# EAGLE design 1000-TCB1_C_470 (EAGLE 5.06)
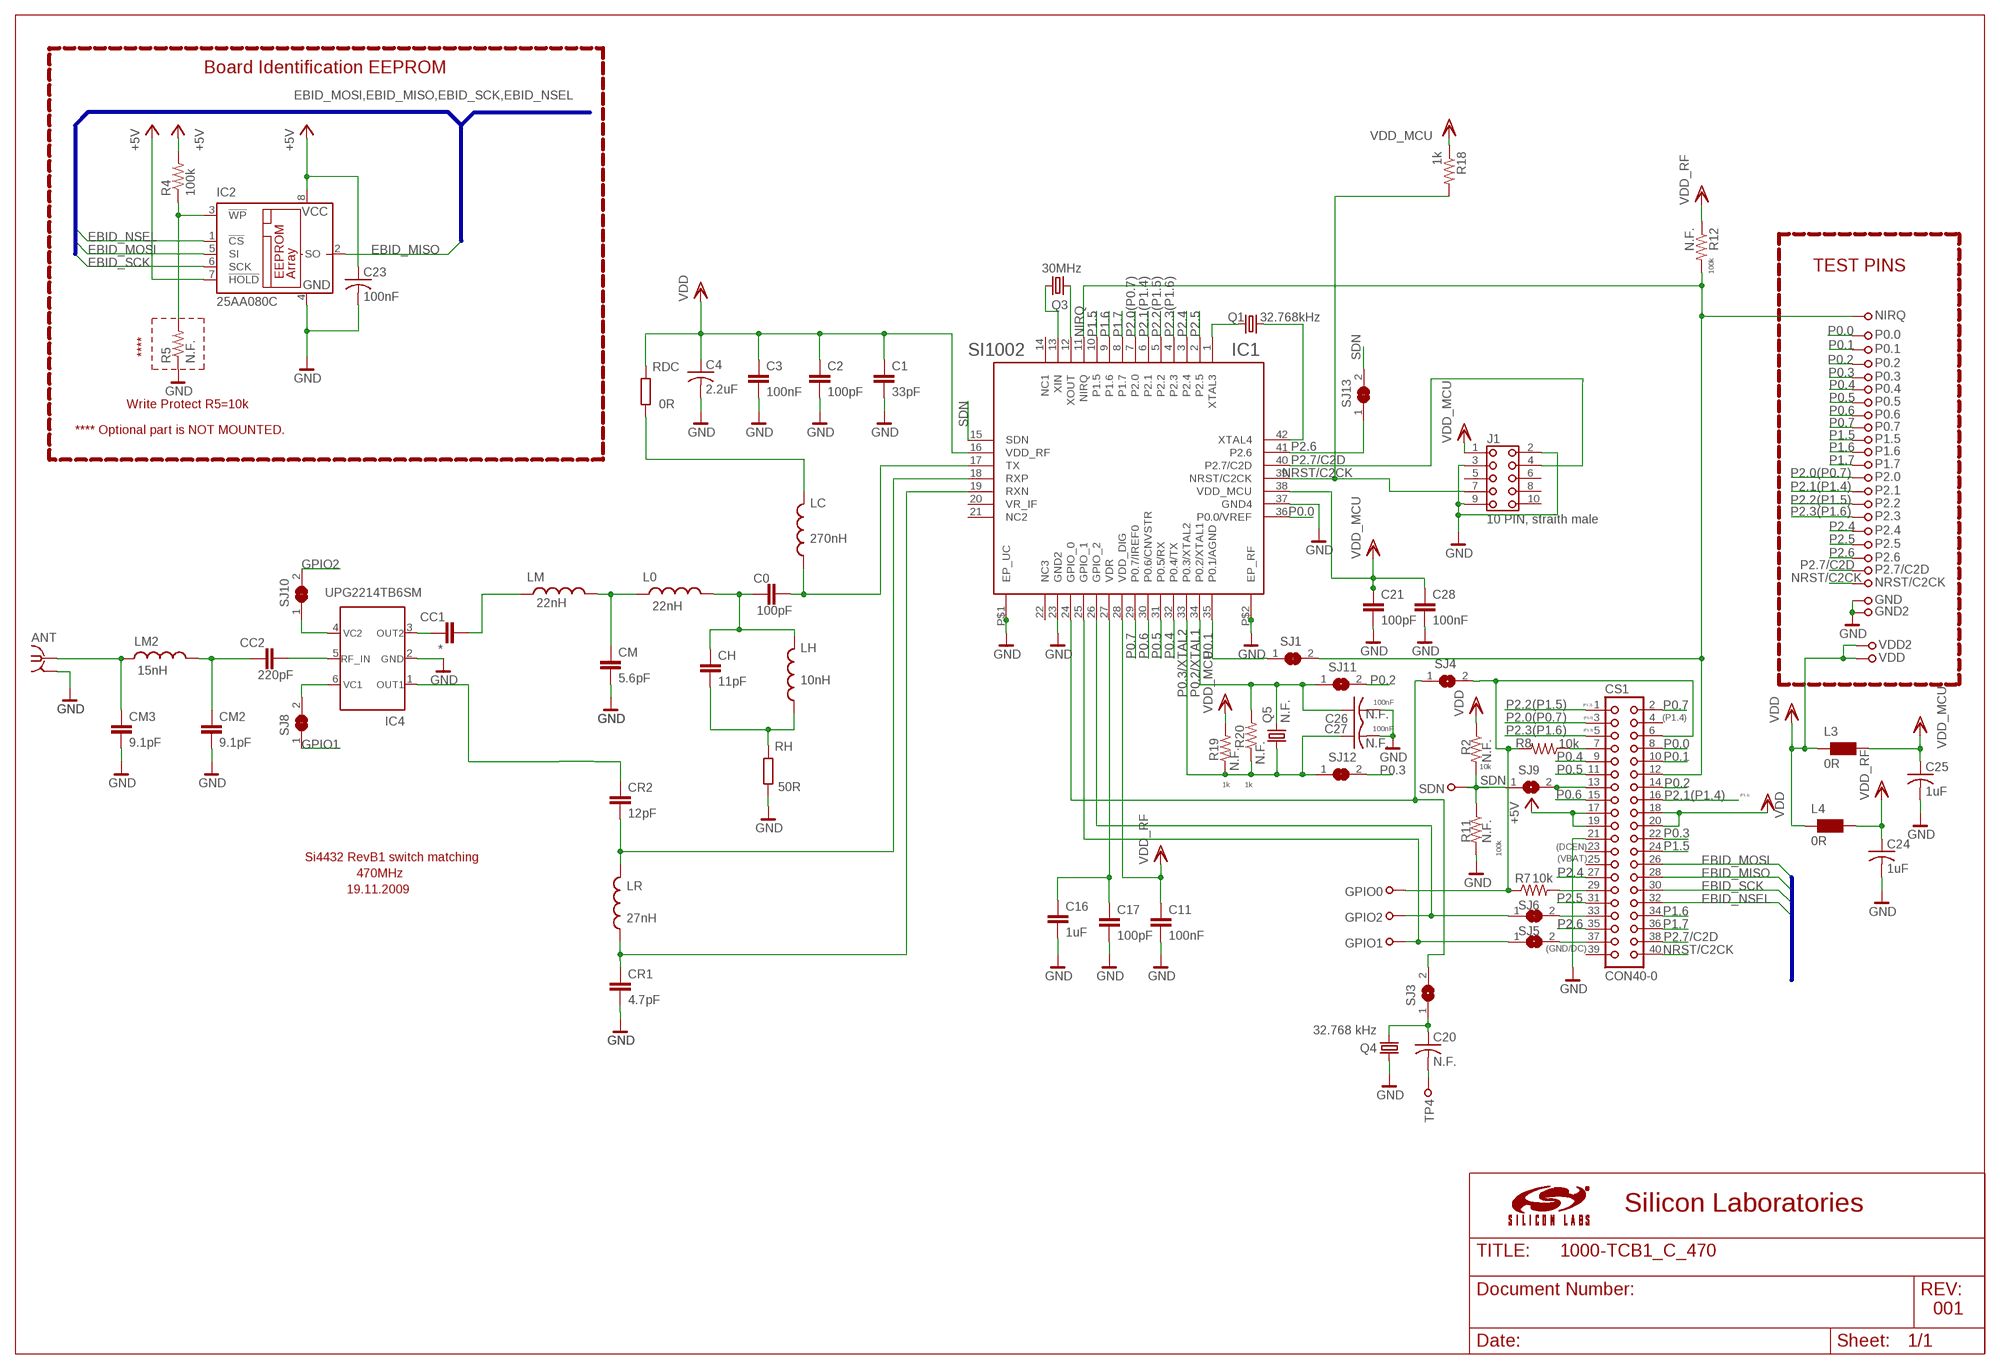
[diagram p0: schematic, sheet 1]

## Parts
ANT  BU-SMA-V  [BU-SMA-V]
C0  100pF  C-EUC0402S  [C0402S]
C1  33pF  C-EUC0402S  [C0402S]
C2  100pF  C-EUC0402S  [C0402S]
C3  100nF  C-EUC0402S  [C0402S]
C4  2.2uF  C-USC0603K  [C0603K]
C11  100nF  C-EUC0402S  [C0402S]
C16  1uF  C-EUC0402S  [C0402S]
C17  100pF  C-EUC0402S  [C0402S]
C20  N.F.  C-USC0603K  [C0603K]
C21  100pF  C-EUC0402S  [C0402S]
C23  100nF  C-USC0603K  [C0603K]
C24  1uF  C-USC0603K  [C0603K]
C25  1uF  C-USC0603K  [C0603K]
C26  N.F.  C-USC0603K  [C0603K]
C27  N.F.  C-USC0603K  [C0603K]
C28  100nF  C-EUC0402S  [C0402S]
CC1  *  C-EUC0402S  [C0402S]
CC2  220pF  C-EUC0402S  [C0402S]
CH  11pF  C-EUC0402S  [C0402S]
CM  5.6pF  C-EUC0402S  [C0402S]
CM2  9.1pF  C-EUC0402S  [C0402S]
CM3  9.1pF  C-EUC0402S  [C0402S]
CR1  4.7pF  C-EUC0402S  [C0402S]
CR2  12pF  C-EUC0402S  [C0402S]
CS1  CON40-0  [PANDUIT-057-040-0-INTEGRATION]
GND  TESTPOINT39MIL  [TESTPOINT1,0]
GND2  TESTPOINT39MIL  [TESTPOINT1,0]
GPIO0  TESTPOINT39MIL  [TESTPOINT1,0]
GPIO1  TESTPOINT39MIL  [TESTPOINT1,0]
GPIO2  TESTPOINT39MIL  [TESTPOINT1,0]
IC1  SI1002  SI1001NORMAL  [QFN42_MCM]
IC2  25AA080C  25AA040ST  [TSSOP8]
IC4  UPG2214TB6SM  [6-PIN_SUPER_MINIMOLD]
J1  10 PIN, straith male  PIN10PANDUIT  [PANDUIT-057-010-1]
L0  22nH  L-USL0402S  [L0402S]
L3  0R  FERRITE  [FERRITE0805]
L4  0R  FERRITE  [FERRITE0805]
LC  270nH  L-USL0402S  [L0402S]
LH  10nH  L-USL0402S  [L0402S]
LM  22nH  L-USL0402S  [L0402S]
LM2  15nH  L-USL0402S  [L0402S]
LR  27nH  L-USL0402S  [L0402S]
NIRQ  TESTPOINT39MIL  [TESTPOINT1,0]
NRST/C2CK  TESTPOINT39MIL  [TESTPOINT1,0]
P0.0  TESTPOINT39MIL  [TESTPOINT1,0]
P0.1  TESTPOINT39MIL  [TESTPOINT1,0]
P0.2  TESTPOINT39MIL  [TESTPOINT1,0]
P0.3  TESTPOINT39MIL  [TESTPOINT1,0]
P0.4  TESTPOINT39MIL  [TESTPOINT1,0]
P0.5  TESTPOINT39MIL  [TESTPOINT1,0]
P0.6  TESTPOINT39MIL  [TESTPOINT1,0]
P0.7  TESTPOINT39MIL  [TESTPOINT1,0]
P1.5  TESTPOINT39MIL  [TESTPOINT1,0]
P1.6  TESTPOINT39MIL  [TESTPOINT1,0]
P1.7  TESTPOINT39MIL  [TESTPOINT1,0]
P2.0  TESTPOINT39MIL  [TESTPOINT1,0]
P2.1  TESTPOINT39MIL  [TESTPOINT1,0]
P2.2  TESTPOINT39MIL  [TESTPOINT1,0]
P2.3  TESTPOINT39MIL  [TESTPOINT1,0]
P2.4  TESTPOINT39MIL  [TESTPOINT1,0]
P2.5  TESTPOINT39MIL  [TESTPOINT1,0]
P2.6  TESTPOINT39MIL  [TESTPOINT1,0]
P2.7/C2D  TESTPOINT39MIL  [TESTPOINT1,0]
Q1  32.768kHz  CRYSTAL-SMD3215_TST  [SMD3215_XTAL]
Q3  30MHz  CRYSTAL-4PINSX-2520-NEW1  [QUARTZ_SIWARD_2520_NEW1]
Q4  32.768 kHz  CRYSTAL32SL  [SMQ32SL]
Q5  N.F.  CRYTALHC49U-V  [HC49U-V]
R2  N.F.  R-US_R0603  [R0603@1]
R4  100k  R-US_R0603  [R0603@1]
R5  N.F.  R-US_R0603  [R0603@1]
R7  10k  R-US_R0603  [R0603@1]
R8  10k  R-US_R0603  [R0603@1]
R11  N.F.  R-US_R0603  [R0603@1]
R12  N.F.  R-US_R0603  [R0603@1]
R18  1k  R-US_R0603  [R0603@1]
R19  1k  R-US_R0603  [R0603@1]
R20  N.F.  R-US_R0603  [R0603@1]
RDC  0R  R-EU_R0402S  [R0402S]
RH  50R  R-EU_R0402S  [R0402S]
SDN  TESTPOINT39MIL  [TESTPOINT1,0]
SJ1  JUMPER_SMD_0402_1  [JUMPER_SMD_0402_1]
SJ3  JUMPER_SMD_0402_OPEN  [JUMPER_SMD_0402_OPEN_1]
SJ4  JUMPER_SMD_0402_OPEN  [JUMPER_SMD_0402_OPEN_1]
SJ5  JUMPER_SMD_0402_1  [JUMPER_SMD_0402_1]
SJ6  JUMPER_SMD_0402_1  [JUMPER_SMD_0402_1]
SJ8  JUMPER_SMD_0402_1  [JUMPER_SMD_0402_1]
SJ9  JUMPER_SMD_0402_OPEN  [JUMPER_SMD_0402_OPEN_1]
SJ10  JUMPER_SMD_0402_1  [JUMPER_SMD_0402_1]
SJ11  JUMPER_SMD_0402_1  [JUMPER_SMD_0402_1]
SJ12  JUMPER_SMD_0402_1  [JUMPER_SMD_0402_1]
SJ13  JUMPER_SMD_0402_1  [JUMPER_SMD_0402_1]
TP4  TESTPOINT39MIL  [TESTPOINT1,0]
VDD  TESTPOINT39MIL  [TESTPOINT1,0]
VDD2  TESTPOINT39MIL  [TESTPOINT1,0]

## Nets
+5V: C23.1 CS1.17 CS1.19 IC2.7(!HOLD) IC2.8(VCC) R4.2
EBID_MISO: CS1.28 IC2.2(SO)
EBID_MOSI: CS1.26 IC2.5(SI)
EBID_NSEL: CS1.32 IC2.1(!CS)
EBID_SCK: CS1.30 IC2.6(SCK)
GND: ANT.2(GND) C1.P$2 C2.P$2 C3.P$2 C4.2 C11.P$2 C16.P$2 C17.P$2 C21.P$2 C23.2 C24.2 C25.2 C26.2 C27.2 C28.P$2 CM2.P$2 CM3.P$2 CM.P$2 CR1.P$2 CS1.21 GND2.1 GND.1 IC1.23(GND2) IC1.37(GND4) IC1.EP1(GND5) IC1.EP2(GND6) IC1.EP3(GND7) IC1.EP4(GND8) IC1.EP5(GND9) IC1.EP6(GND10) IC1.EP7(GND11) IC1.EP8(GND12) IC1.P$1(EP_UC) IC1.P$2(EP_RF) IC2.4(GND) IC4.2 J1.2 J1.3 J1.9 Q4.1 R5.1 R11.2 RH.P$1
GPIO0: CS1.6 GPIO0.1 R7.1 R8.2 SJ4.2
GPIO1: GPIO1.1 IC1.25(GPIO_1) SJ5.1 SJ8.1
GPIO2: GPIO2.1 IC1.26(GPIO_2) SJ6.1 SJ10.2
N$1: C0.P$2 IC1.17(TX) LC.P$1
N$5: CS1.29 R7.2
N$6: CS1.33 SJ6.2
N$8: CS1.37 SJ5.2
N$9: CS1.7 R8.1
N$11: C0.P$1 CH.P$1 L0.P$2 LH.P$2
N$13: C20.1 Q4.4 SJ3.1
N$14: CC2.P$1 CM2.P$1 LM2.P$2
N$19: IC1.24(GPIO_0) SJ3.2 SJ4.1
N$20: CR2.P$2 IC1.18(RXP) LR.P$2
N$22: CR1.P$1 IC1.19(RXN) LR.P$1
N$23: LC.P$2 RDC.P$1
N$25: CC2.P$2 IC4.5
N$26: C20.2 TP4.1
N$29: IC4.6 SJ8.2
N$32: CC1.P$1 IC4.3
N$33: CH.P$2 LH.P$1 RH.P$2
N$34: IC1.12(XOUT) Q3.3
N$35: IC1.13(XIN) Q3.1
N$36: C16.P$1 C17.P$1 IC1.27(VDR)
N$38: IC4.4 SJ10.1
N$39: CC1.P$2 LM.P$1
N$41: IC2.3(!WP) R4.1 R5.2
N$45: IC1.1(XTAL3) Q1.X2
N$46: IC1.42(XTAL4) Q1.X1
N$48: CS1.13 SJ9.2
NIRQ: CS1.12 IC1.11(NIRQ) NIRQ.1 R12.2 SJ1.2
NRST/C2CK: CS1.40 IC1.39(NRST/C2CK) J1.7 NRST/C2CK.1 R18.2
P0.0: CS1.8 IC1.36(P0.0/VREF) P0.0.1
P0.1: CS1.10 IC1.35(P0.1/AGND) P0.1.1 SJ1.1
P0.2: CS1.14 P0.2.1 SJ11.2
P0.2/XTAL1: C26.1 IC1.34(P0.2/XTAL1) Q5.2 R20.2 SJ11.1
P0.3: CS1.22 P0.3.1 SJ12.2
P0.3/XTAL2: C27.1 IC1.33(P0.3/XTAL2) Q5.1 R19.1 R20.1 SJ12.1
P0.4: CS1.9 IC1.32(P0.4/TX) P0.4.1
P0.5: CS1.11 IC1.31(P0.5/RX) P0.5.1
P0.6: CS1.15 IC1.30(P0.6/CNVSTR) P0.6.1
P0.7: CS1.2 IC1.29(P0.7/IREF0) P0.7.1
P1.5: CS1.24 IC1.10(P1.5) P1.5.1
P1.6: CS1.34 IC1.9(P1.6) P1.6.1
P1.7: CS1.36 IC1.8(P1.7) P1.7.1
P2.0(P0.7): CS1.3 IC1.7(P2.0) P2.0.1
P2.1(P1.4): CS1.16 IC1.6(P2.1) P2.1.1
P2.2(P1.5): CS1.1 IC1.5(P2.2) P2.2.1
P2.3(P1.6): CS1.5 IC1.4(P2.3) P2.3.1
P2.4: CS1.27 IC1.3(P2.4) P2.4.1
P2.5: CS1.31 IC1.2(P2.5) P2.5.1
P2.6: CS1.35 IC1.41(P2.6) P2.6.1 SJ13.1
P2.7/C2D: CS1.38 IC1.40(P2.7/C2D) J1.4 P2.7/C2D.1
RX: CR2.P$1 IC4.1
SDN: IC1.15(SDN) R2.2 R11.1 SDN.1 SJ9.1 SJ13.2
TX: ANT.1 CM3.P$1 LM2.P$1
TX3: CM.P$1 L0.P$1 LM.P$2
VCC_MCU: C21.P$1 C25.1 C28.P$1 IC1.38(VDD_MCU) J1.1 L3.2 R18.1 R19.2 ; supply symbol labelled VDD_MCU
VDD: C1.P$1 C2.P$1 C3.P$1 C4.1 CS1.18 CS1.20 IC1.16(VDD_RF) L3.1 L4.1 R2.1 RDC.P$2 VDD2.1 VDD.1
VDD_RF: C11.P$1 C24.1 IC1.28(VDD_DIG) L4.2 R12.1
Unconnected: CS1.4 CS1.23 CS1.25 CS1.39 IC1.14(NC1) IC1.21(NC2) IC1.22(NC3) J1.5 J1.6 J1.8 J1.10

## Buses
EBID_MOSI,EBID_MISO,EBID_SCK,EBID_NSEL

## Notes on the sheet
- Board Identification EEPROM
- 100k | TEST PINS
- ****
- Write Protect R5=10k
- **** Optional part is NOT MOUNTED.
- 100nF
- (P1.2)
- N.F. | (P1.0)
- (P1.4)
- 100nF | (P1.3)
- N.F.
- N.F. | N.F.
- 10k
- 1k | 1k
- (P1.1)
- (DCEN)
- 100k
- Si4432 RevB1 switch matching | (VBAT)
- 470MHz
- 19.11.2009
- (GND/DC)
- Silicon Laboratories
- 001

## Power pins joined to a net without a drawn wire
GND: ANT.3(GND) ANT.4(GND) ANT.5(GND) Q3.2(GND) Q3.4(GND)
VR_IF: IC1.20(VR_IF)

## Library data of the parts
ANT = lve:BU-SMA-V: FEMALE SMA CONNECTOR Radiall distributor RS 112-3794
C0 C1-C3 C11 C16 C17 C21 C28 CC1 CC2 CH CM CM2 CM3 CR1 CR2 = rcl:C-EU: CAPACITOR, European symbol
C4 C20 C23-C27 = rcl:C-US: CAPACITOR, American symbol
CS1 = lve:CON40
GND GND2 GPIO0 GPIO1 GPIO2 NIRQ NRST/C2CK P0.0 P0.1-P0.7 P1.5-P1.7 P2.0 P2.1-P2.6 P2.7/C2D SDN TP4 VDD VDD2 = lve:TESTPOINT
IC1 = SiLabsMCU:SI1001
IC2 = microchip:25*: Serial EEPROM 4 K, SPI bus
IC4 = lve:UPG2214TB
J1 = lve:PIN10
L0 LC LH LM LM2 LR = rcl:L-US: INDUCTOR, American symbol
L3 L4 = lve:FERRITE
Q1 = dzo:CRYSTAL-SMD3215_TST
Q3 = lve:CRYSTAL-4PIN
Q4 = lve:CRYSTAL
Q5 = mlu:CRYTAL: CRYSTAL
R2 R4 R5 R7 R8 R11 R12 R18-R20 = rcl:R-US_: RESISTOR, American symbol
RDC RH = rcl:R-EU_: RESISTOR, European symbol
SJ1 SJ5 SJ6 SJ8 SJ10-SJ13 = tab:JUMPER_SMD_0402_1
SJ3 SJ4 SJ9 = tab:JUMPER_SMD_0402_OPEN

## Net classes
1 dgnd: clearance 0.508 mm

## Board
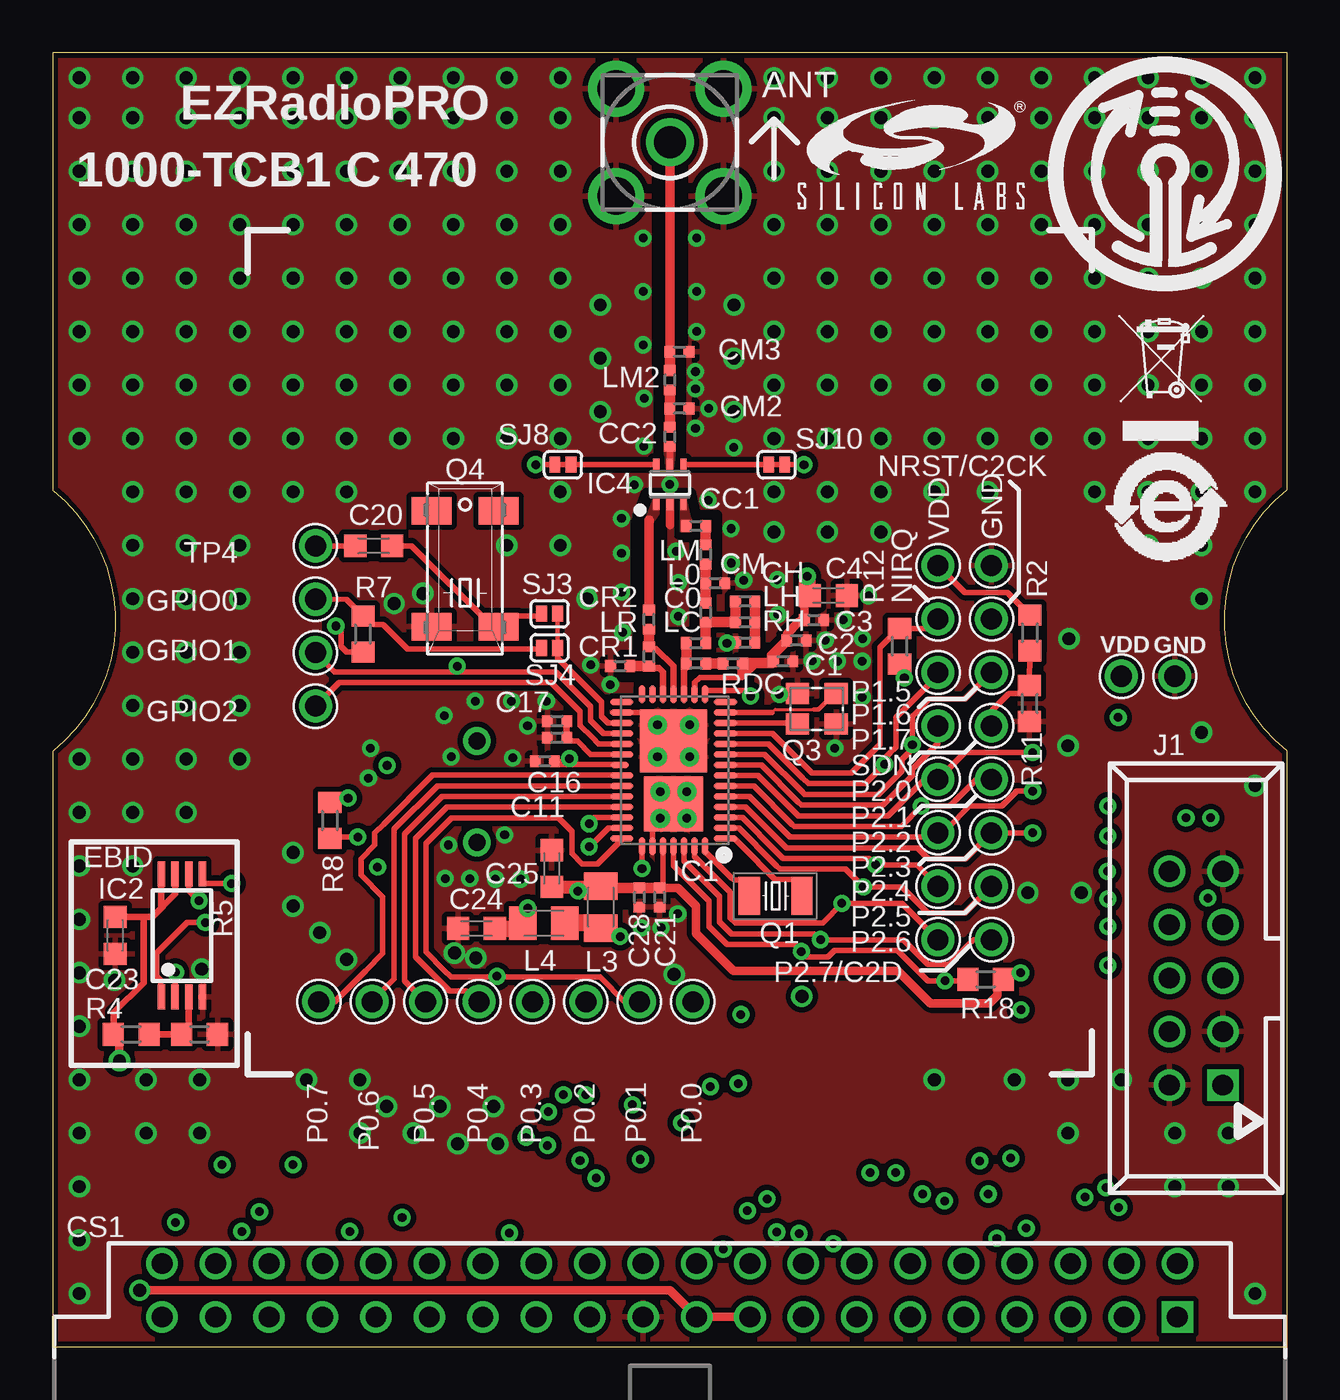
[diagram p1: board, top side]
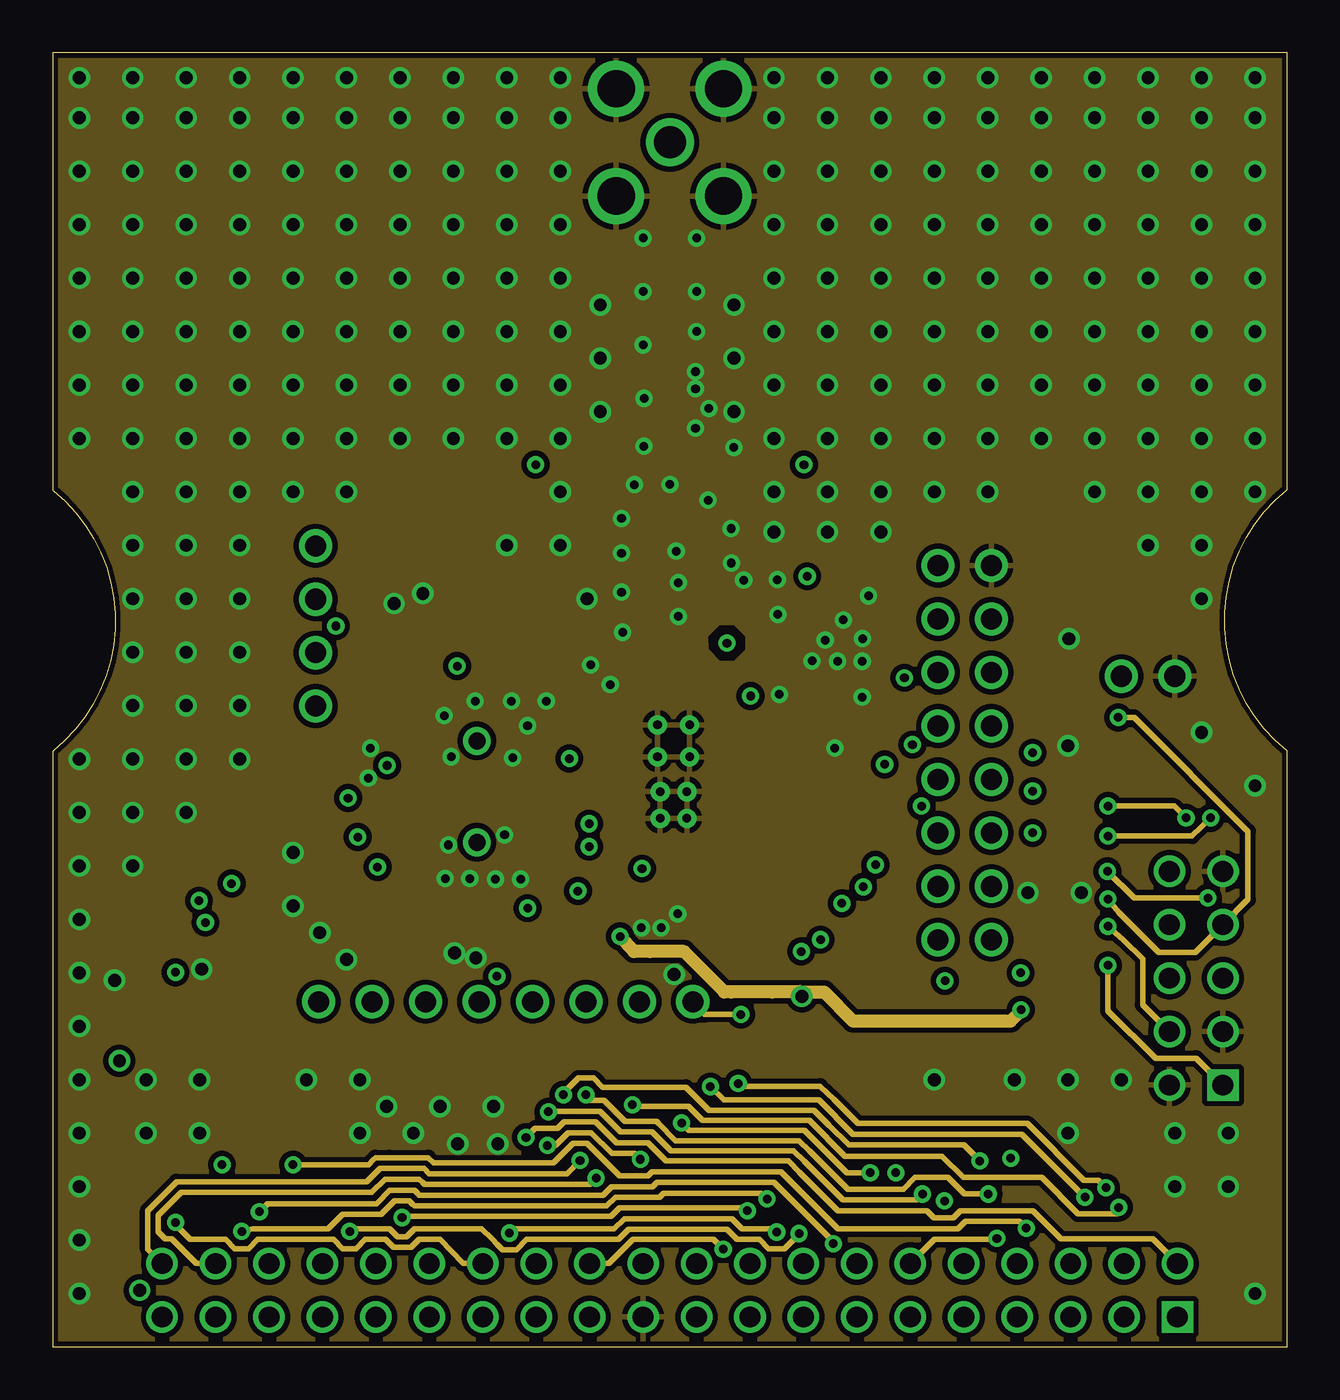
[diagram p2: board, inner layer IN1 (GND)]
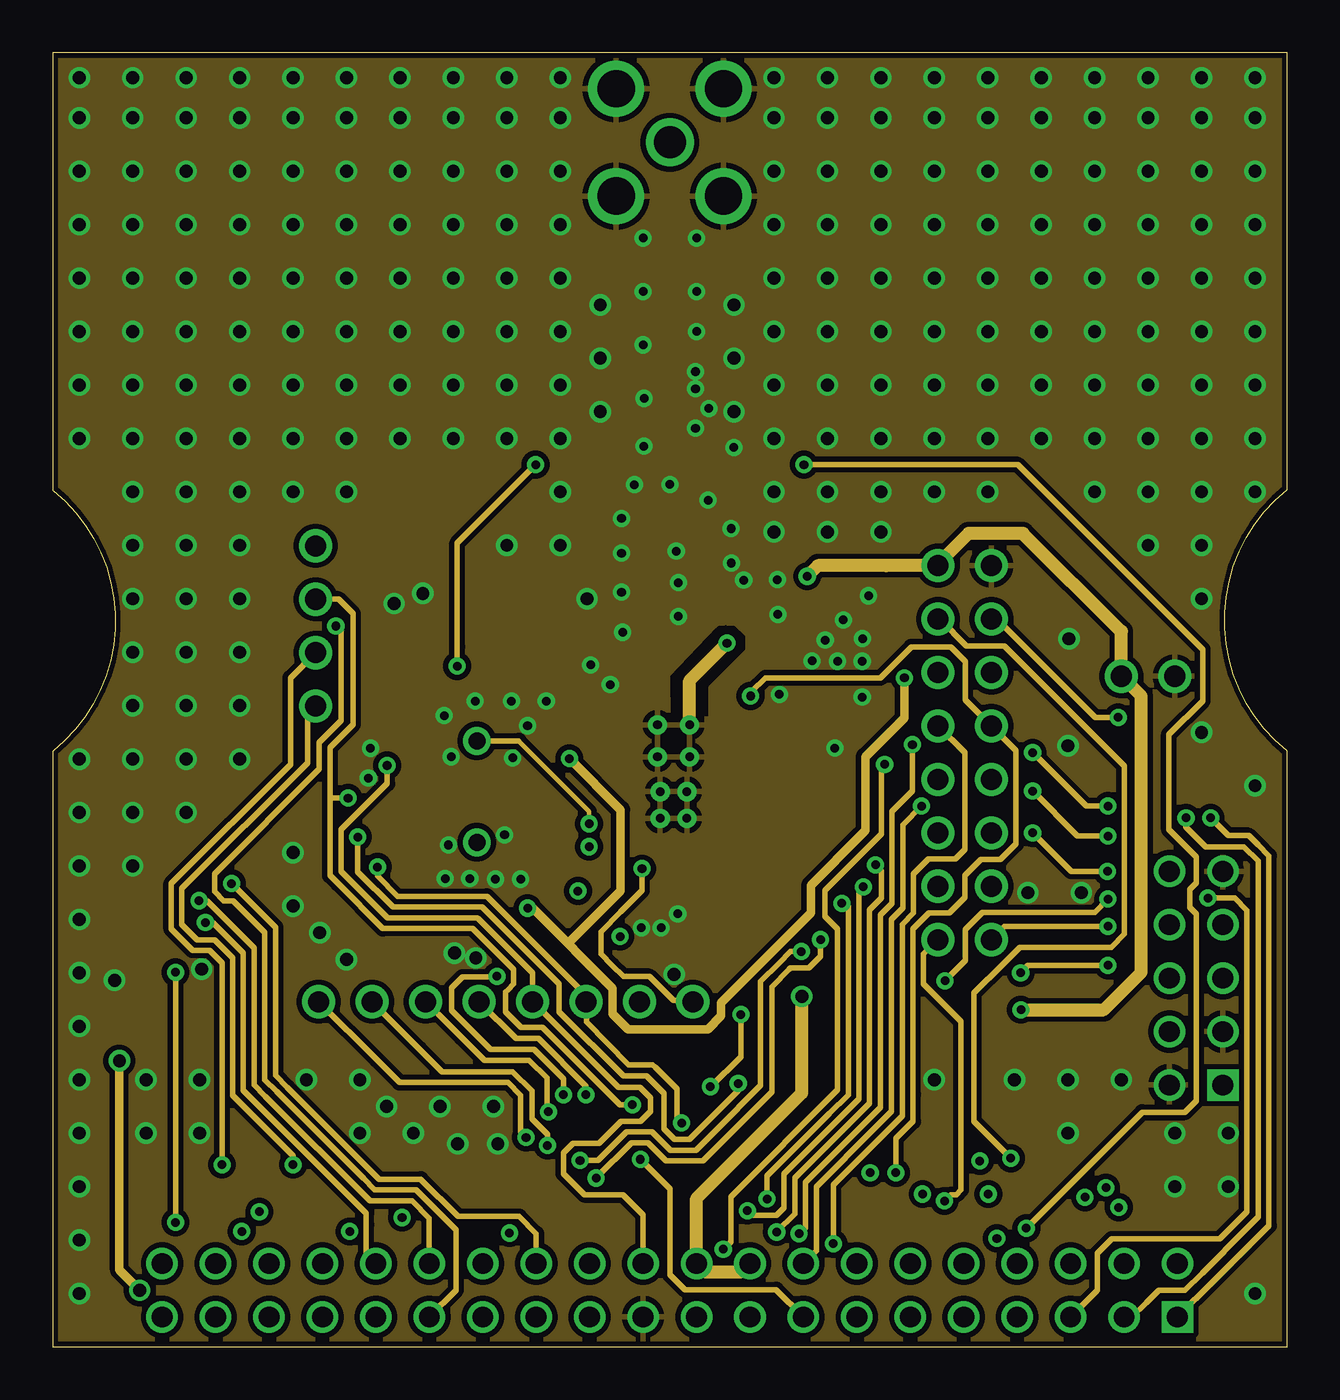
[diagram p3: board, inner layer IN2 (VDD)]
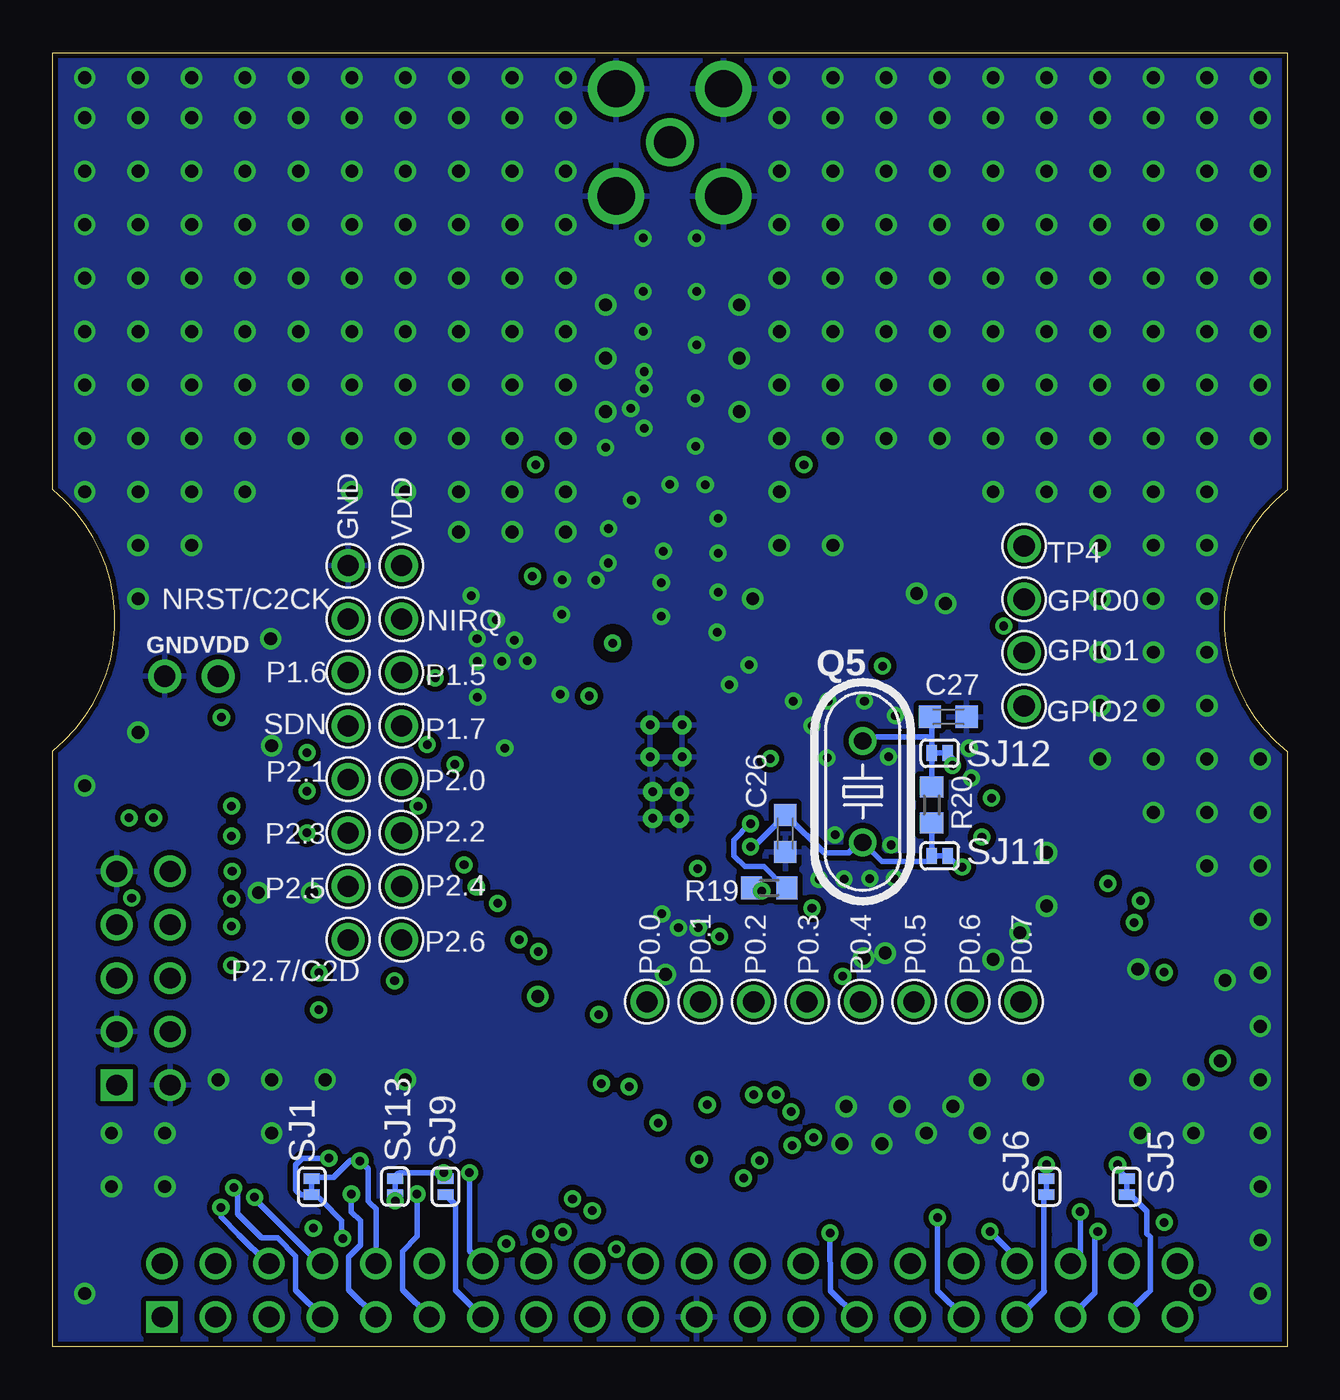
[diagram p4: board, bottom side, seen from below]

Size 58.67 x 61.52 mm. Coordinates in mm from the lower left corner, seen from the top.
Outline: 0,28.3 0,0 58.67,0 58.67,28.32 arc-102 58.67,40.74 58.67,61.52 0,61.52 0,40.72 0.03,40.69 arc-102 0,28.3
Copper layers (1*2*3*16): Top 0.0356mm / dielectric 0.5mm / IN1 (GND) 0.0356mm / dielectric 0.5mm / IN2 (VDD) 0.0356mm / dielectric 0.5mm / Bottom 0.0356mm
Design rules "TAMARA *": minimum track width 8mil, minimum drill 13mil, track to track 10mil, track to pad 10mil, pad to pad 10mil, via to via 10mil, smd to smd 0mil, copper to edge 10mil, drill to drill 8mil, minimum pad ring 10mil, minimum via ring 8mil, stop-mask expansion 4mil, vias tented up to drill 24mil, thermal gap 10mil
tRestrict: 34 lines
bRestrict: area 31.4,32.8 to 32.7,34.1; 2 lines

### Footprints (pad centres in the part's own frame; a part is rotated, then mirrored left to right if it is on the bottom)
BU-SMA-V = drill 1.524 pad 2.286 round: 1 0,0 | drill 1.778 pad 2.667 round: 2 -2.55,2.55; 3 2.55,2.55; 4 2.55,-2.55; 5 -2.55,-2.55
C0402S = smd 0.508 x 0.559: P$1 -0.457,0; P$2 0.457,0
C0603K = smd 1.05 x 1.08: 1 -0.875,0; 2 0.875,0
PANDUIT-057-040-0-INTEGRATION = drill 0.991 square: 1 -24.13,-1.27 | drill 0.991 round: 2 -24.13,-3.81; 3 -21.59,-1.27; 4 -21.59,-3.81; 5 -19.05,-1.27; 6 -19.05,-3.81; 7 -16.51,-1.27; 8 -16.51,-3.81; 9 -13.97,-1.27; 10 -13.97,-3.81; 11 -11.43,-1.27; 12 -11.43,-3.81; 13 -8.89,-1.27; 14 -8.89,-3.81; 15 -6.35,-1.27; 16 -6.35,-3.81; 17 -3.81,-1.27; 18 -3.81,-3.81; 19 -1.27,-1.27; 20 -1.27,-3.81; 21 1.27,-1.27; 22 1.27,-3.81; 23 3.81,-1.27; 24 3.81,-3.81; 25 6.35,-1.27; 26 6.35,-3.81; 27 8.89,-1.27; 28 8.89,-3.81; 29 11.43,-1.27; 30 11.43,-3.81; 31 13.97,-1.27; 32 13.97,-3.81; 33 16.51,-1.27; 34 16.51,-3.81; 35 19.05,-1.27; 36 19.05,-3.81; 37 21.59,-1.27; 38 21.59,-3.81; 39 24.13,-1.27; 40 24.13,-3.81
TESTPOINT1,0 = drill 1 pad 1.575 round: 1 0,0
QFN42_MCM = smd 1.1 x 0.3: 1 -2.46,3.25; 2 -2.46,2.75; 3 -2.46,2.25; 4 -2.46,1.75; 5 -2.46,1.25; 6 -2.46,0.75; 7 -2.46,0.25; 8 -2.46,-0.25; 9 -2.46,-0.75; 10 -2.46,-1.25; 11 -2.46,-1.75; 12 -2.46,-2.25; 13 -2.46,-2.75; 14 -2.46,-3.25; 22 2.46,-3.25; 23 2.46,-2.75; 24 2.46,-2.25; 25 2.46,-1.75; 26 2.46,-1.25; 27 2.46,-0.75; 29 2.46,0.25; 30 2.46,0.75; 31 2.46,1.25; 32 2.46,1.75; 33 2.46,2.25; 34 2.46,2.75; 35 2.46,3.25 | smd 0.3 x 0.85: 15 -1.5,-3.61; 16 -1,-3.61; 17 -0.5,-3.61; 18 0,-3.61; 19 0.5,-3.61; 20 1,-3.61; 21 1.5,-3.61; 36 1.5,3.61; 37 1,3.61; 38 0.5,3.61; 39 0,3.61; 40 -0.5,3.61; 41 -1,3.61; 42 -1.5,3.61 | smd 0.85 x 0.3: 28 2.56,-0.25 | drill 0.406 round: EP1 -0.635,2.286; EP2 0.635,2.286; EP3 -0.635,1.016; EP4 0.635,1.016; EP5 -0.762,-0.635; EP6 0.762,-0.635; EP7 -0.762,-2.159; EP8 0.762,-2.159 | smd 2.8 x 2.6: P$1 0,1.6 | smd 3.2 x 3: P$2 0,-1.4
TSSOP8 = smd 0.35 x 1.2: 1 -0.975,-2.925; 2 -0.325,-2.925; 3 0.325,-2.925; 4 0.975,-2.925; 5 0.975,2.925; 6 0.325,2.925; 7 -0.325,2.925; 8 -0.975,2.925
6-PIN_SUPER_MINIMOLD = smd 0.55 x 0.3: 1 -0.948,0.65; 2 -0.948,0; 3 -0.948,-0.65; 4 0.948,-0.65; 5 0.948,0; 6 0.948,0.65
PANDUIT-057-010-1 = drill 0.991 square: 1 -5.08,-1.27 | drill 0.991 round: 2 -5.08,1.27; 3 -2.54,-1.27; 4 -2.54,1.27; 5 0,-1.27; 6 0,1.27; 7 2.54,-1.27; 8 2.54,1.27; 9 5.08,-1.27; 10 5.08,1.27
L0402S = smd 0.508 x 0.559: P$1 -0.457,0; P$2 0.457,0
FERRITE0805 = smd 1.3 x 1.6: 1 -1,0; 2 1,0
SMD3215_XTAL = smd 1 x 1.8: X1 -1.23,0.016; X2 1.27,0.016
QUARTZ_SIWARD_2520_NEW1 = smd 1.1 x 1: 1 -0.925,-0.725; 2 0.925,-0.725; 3 0.925,0.725; 4 -0.925,0.725
SMQ32SL = smd 1.3 x 1.9: 1 -2.75,1.6; 2 2.75,1.6; 3 2.75,-1.6; 4 -2.75,-1.6
HC49U-V = drill 0.813 round: 1 -2.413,0; 2 2.413,0
R0603@1 = smd 1 x 1.1: 1 -0.85,0; 2 0.85,0
R0402S = smd 0.508 x 0.559: P$1 -0.457,0; P$2 0.457,0
JUMPER_SMD_0402_1 = smd 0.508 x 0.762: 1 -0.381,0; 2 0.381,0
JUMPER_SMD_0402_OPEN_1 = smd 0.508 x 0.762: 1 -0.381,0; 2 0.381,0

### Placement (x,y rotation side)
ANT  29.34,57.25 0 top
C0  30.58,33.45 180 top
C1  34.72,32.59 0 top
C2  35.36,33.58 0 top
C3  36.2,34.54 0 top
C4  36.88,35.71 0 top
C11  23.39,27.84 180 top
C16  23.98,28.96 180 top
C17  23.98,29.74 180 top
C20  15.27,38.07 180 top
C21  28.85,21.36 270 top
C23  2.97,19.56 270 top
C24  20.14,19.89 180 top
C25  23.72,22.73 90 top
C26  23.85,24.41 270 bottom
C27  16.1,29.95 0 bottom
C28  27.89,21.36 270 top
CC1  30.58,39.01 0 top
CC2  29.34,43.26 270 top
CH  32.92,35.43 0 top
CM  31.5,36.3 0 top
CM2  29.79,44.6 0 top
CM3  29.79,47.29 0 top
CR1  26.97,32.36 180 top
CR2  28.35,34.57 270 top
CS1  29.34,0.15 180 top
E$1  [TRANSCEIVE-ICON06]  52.86,56.06 0 top
GND  44.63,37.13 0 top
GND2  53.34,31.88 0 top
GPIO0  12.5,35.53 0 top
GPIO1  12.5,32.99 0 top
GPIO2  12.5,30.45 0 top
IC1  29.51,27.41 180 top
IC2  6.15,19.56 0 top
IC4  29.34,41 90 top
J1  54.36,17.53 90 top
L0  31.04,34.9 270 top
L3  26.06,20.9 90 top
L4  23.34,20.14 180 top
LC  30.58,32.49 0 top
LH  32.92,34.44 180 top
LM  31.04,37.67 270 top
LM2  29.34,45.95 270 top
LR  28.35,32.82 90 top
NIRQ  42.09,34.59 180 top
NRST/C2CK  44.63,34.59 0 top
P0.0  30.43,16.41 0 top
P0.1  27.89,16.41 0 top
P0.2  25.35,16.41 0 top
P0.3  22.81,16.41 0 top
P0.4  20.27,16.41 0 top
P0.5  17.73,16.41 0 top
P0.6  15.19,16.41 0 top
P0.7  12.65,16.41 0 top
P1.5  42.09,32.05 0 top
P1.6  44.63,32.05 0 top
P1.7  42.09,29.51 0 top
P2.0  42.09,26.97 0 top
P2.1  44.63,26.97 0 top
P2.2  42.09,24.43 0 top
P2.3  44.63,24.43 0 top
P2.4  42.09,21.89 0 top
P2.5  44.63,21.89 0 top
P2.6  42.09,19.35 0 top
P2.7/C2D  44.63,19.35 0 top
Q1  34.34,21.41 0 top
Q3  36.32,30.33 180 top
Q4  19.61,36.98 90 top
Q5  20.17,26.39 270 bottom
R2  46.45,33.94 270 top
R4  3.73,14.86 180 top
R5  6.99,14.86 180 top
R7  14.76,33.88 270 top
R8  13.18,25.02 90 top
R11  46.43,30.58 270 top
R12  40.26,33.3 90 top
R18  44.35,17.48 180 top
R19  24.61,21.82 180 bottom
R20  16.89,25.76 270 bottom
RDC  32.33,32.49 0 top
RH  32.92,33.48 0 top
SDN  44.63,29.51 0 top
SJ1  46.35,7.62 270 bottom
SJ3  23.62,34.85 0 top
SJ4  23.62,33.22 180 top
SJ5  7.62,7.62 270 bottom
SJ6  11.43,7.62 270 bottom
SJ8  24.26,41.94 0 top
SJ9  40.01,7.62 270 bottom
SJ10  34.42,41.94 0 top
SJ11  16.51,23.34 0 bottom
SJ12  16.51,28.22 0 bottom
SJ13  42.39,7.62 90 bottom
TP4  12.5,38.07 0 top
U$1  SILABS_LOGO  [SILABS_LOGO]  34.47,53.59 0 top
U$5  [ROHS_CHINA]  53.01,40.01 0 top
U$27  [NON-DISPOSABLE]  52.7,46.96 0 top
VDD  42.09,37.13 0 top
VDD2  50.8,31.88 0 top

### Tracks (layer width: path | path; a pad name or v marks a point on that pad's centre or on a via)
+5V  (via drill 0.61)
  Top 0.254: 4.33,20.43 4.32,20.45
  Top 0.305: IC2.8 5.17,20.87 4.75,20.45 | C23.1 3.48,20.45 4.32,20.45 4.75,20.45 | IC2.7 5.82,21.52 4.75,20.45 | R4.2 2.9,15.9 4.33,17.31 4.33,20.43
  Top 0.406: CS1.17 CS1.19 29.34,2.69 v4.14,2.69 | v3.17,13.6 3.17,14.66 3.17,14.86 R4.2
  IN2 (VDD) 0.406: v4.14,2.69 3.17,3.66 v3.17,13.6
EBID_MISO  (via drill 0.41)
  Top 0.254: IC2.2 5.82,17.89 v5.84,17.8
  IN1 (GND) 0.254: CS1.28 19.51,3.96 18.41,5.11 17.42,5.11 17.04,4.72 16.2,4.72 15.82,5.11 15.24,5.11 14.86,5.11 14.43,4.67 13.79,4.67 13.36,5.11 9.75,5.11 9.32,4.67 8.66,4.67 8.23,5.11 6.53,5.11 5.84,5.79 v5.84,5.92
  IN2 (VDD) 0.254: v5.84,5.92 v5.84,17.8
EBID_MOSI  (via drill 0.41 pad 0.81)
  Top 0.254: IC2.5 7.16,22.48 7.11,22.43 7.11,22.02 v8.51,22.02
  IN2 (VDD) 0.254: 8.48,21.95 v8.51,22.02 10.59,19.94 10.59,12.9 11.15,12.34 15.52,7.98 17.5,7.98 19.28,6.2 22.17,6.2 22.99,5.38 CS1.26
EBID_NSEL  (via drill 0.41)
  Top 0.254: 5.18,16.36 5.18,16.62 IC2.1 5.13,16.67 5.13,17.42 4.95,17.6 4.95,18.72 5.33,19.1 6.4,20.17 v7.26,20.17
  IN2 (VDD) 0.254: CS1.32 14.91,4.42 14.91,5.82 14.91,6.35 9.6,11.66 9.07,12.19 9.07,18.19 9.07,18.72 8.05,19.74 7.62,20.17 v7.26,20.17
EBID_SCK  (via drill 0.41 pad 0.81)
  Top 0.254: 6.48,22.61 IC2.6 6.48,21.69 v6.96,21.21
  IN2 (VDD) 0.254: CS1.30 17.91,6.1 17.08,6.93 16.08,6.93 15.09,6.93 10.11,11.91 9.58,12.45 9.58,18.62 9.58,18.97 7.87,20.68 7.34,21.21 v6.96,21.21
GND  (via drill 0.41 pad 0.81, 0.61, 0.61 pad 1.02)
  Top 0.203: IC1.P$2 29.52,28.78 28.8,29.49 28.75,29.54 IC1.P$2
  Top 0.254: IC1.P$1 28.88,25.09 28.52,24.73 IC1.37 | 28.83,29.49 IC1.P$2 28.82,29.5 28.16,30.16 IC1.23
  Top 0.406: IC1.P$2 29.46,28.81 | 28.82,29.5 28.8,29.5 28.8,29.49 28.8,29.57 IC1.EP8 | IC1.EP2 28.88,25.09 | 29.34,39.06 v29.34,41 | RH.P$1 32.05,33.48 v32.05,33.45
  Top 0.508: v25.57,32.42 25.74,32.44
  IN2 (VDD) 0.61: v32.05,33.45 30.28,31.67 30.28,29.59
  other vias: 1.27,2.54 38.48,30.89 36.1,32.61 38.48,32.59 37.58,34.56 36.72,33.59 38.5,33.67 34.54,31.01 2.95,17.42 6.99,10.16 38.78,35.7 29.71,20.58 27.99,19.92 34.48,34.82 34.45,36.47 32.27,37.26 27.09,33.97 32.25,38.9 37.18,28.46 22.25,22.23 18.66,22.26 22.58,29.52 18.61,30 21.48,24.34 18.94,28.05 1.27,5.08 1.27,7.62 1.27,12.7 1.27,15.24 1.27,17.78 1.27,20.32 1.27,22.86 1.27,25.4 3.81,27.94 3.81,25.4 6.35,25.4 6.35,27.94 8.89,27.94 3.81,22.86 3.81,30.48 6.35,30.48 8.89,30.48 6.35,33.02 3.81,33.02 3.81,35.56 6.35,35.56 8.89,35.56 8.89,33.02 13.97,40.64 11.43,40.64 8.89,38.1 6.35,38.1 3.81,38.1 3.81,40.64 8.89,40.64 8.89,43.18 8.89,45.72 6.35,45.72 3.81,45.72 3.81,43.18 1.27,45.72 1.27,48.26 1.27,50.8 1.27,53.34 1.27,55.88 3.81,55.88 3.81,53.34 3.81,50.8 3.81,48.26 3.81,58.42 3.81,60.33 1.27,60.33 1.27,58.42 8.89,48.26 8.89,58.42 8.89,55.88 8.89,53.34 8.89,50.8 8.89,60.33 6.35,43.18 6.35,55.88 6.35,53.34 6.35,50.8 6.35,48.26 6.35,58.42 6.35,60.33 16.51,45.72 16.51,43.18 16.51,55.88 16.51,53.34 16.51,50.8 16.51,48.26 16.51,58.42 16.51,60.33 19.05,45.72 19.05,43.18 19.05,55.88 19.05,53.34 19.05,50.8 19.05,48.26 19.05,58.42 19.05,60.33 21.59,45.72 21.59,43.18 21.59,55.88 21.59,53.34 21.59,50.8 21.59,48.26 21.59,58.42 21.59,60.33 24.13,45.72 24.13,43.18 24.13,55.88 24.13,53.34 24.13,50.8 24.13,48.26 24.13,58.42 24.13,60.33 13.97,45.72 13.97,43.18 13.97,55.88 13.97,53.34 13.97,50.8 13.97,48.26 13.97,58.42 13.97,60.33 11.43,45.72 11.43,43.18 11.43,55.88 11.43,53.34 11.43,50.8 11.43,48.26 11.43,58.42 11.43,60.33 41.91,45.72 39.37,45.72 36.83,45.72 34.29,45.72 34.29,48.26 34.29,50.8 34.29,53.34 34.29,55.88 36.83,55.88 36.83,53.34 36.83,50.8 36.83,48.26 36.83,58.42 36.83,60.33 34.29,60.33 34.29,58.42 41.91,48.26 41.91,58.42 41.91,55.88 41.91,53.34 41.91,50.8 41.91,60.33 39.37,55.88 39.37,53.34 39.37,50.8 39.37,48.26 39.37,58.42 39.37,60.33 49.53,45.72 49.53,55.88 49.53,53.34 49.53,50.8 49.53,48.26 49.53,58.42 49.53,60.33 52.07,45.72 52.07,55.88 52.07,53.34 52.07,50.8 52.07,48.26 52.07,58.42 52.07,60.33 54.61,45.72 54.61,55.88 54.61,53.34 54.61,50.8 54.61,48.26 54.61,58.42 54.61,60.33 57.15,45.72 57.15,55.88 57.15,53.34 57.15,50.8 57.15,48.26 57.15,58.42 57.15,60.33 46.99,45.72 46.99,55.88 46.99,53.34 46.99,50.8 46.99,48.26 46.99,58.42 46.99,60.33 44.45,45.72 44.45,55.88 44.45,53.34 44.45,50.8 44.45,48.26 44.45,58.42 44.45,60.33 41.91,43.18 39.37,43.18 49.53,40.64 49.53,43.18 52.07,40.64 52.07,43.18 54.61,40.64 54.61,43.18 57.15,43.18 46.99,43.18 44.45,43.18 39.37,38.73 52.07,38.1 54.61,38.1 36.83,43.18 34.29,43.18 24.13,38.1 21.59,38.1 57.15,2.54 29.64,37.82 26.51,31.48 28.07,47.62 30.61,52.7 30.56,46.35 31.19,44.6 32.38,42.75 36.83,38.73 39.37,40.64 41.91,40.64 44.45,40.64 34.29,38.73 15.01,27.03 15.11,28.46 16.23,35.33 21.81,30.69 23.46,30.69 20.09,30.69 21.86,28 21.16,9.65 20.12,18.49 19.83,22.26 21.05,22.23 18.82,23.86 17.6,35.81 18.41,11.43 17.14,10.16 15.88,11.43 28.93,19.92 29.54,17.7 48.31,33.66 37.31,32.59 28.11,42.81 28.12,45.09 31.16,40.24 32.85,36.44 24.13,40.64 34.29,40.64 36.83,40.64 7.09,17.96 53.34,10.16 55.88,10.16 55.88,7.62 11.43,23.5 11.43,20.95 19.25,9.65 20.95,11.43 14.61,10.16 14.61,12.7 12.06,12.7 50.8,12.7 48.26,12.7 41.91,12.7 53.34,7.62 46.35,21.59 48.26,28.57 54.61,35.56 54.61,29.21 57.15,26.67 13.97,18.41 12.7,19.68 19.1,18.72 6.35,40.64 1.27,43.18 57.15,40.64 6.99,12.7 4.45,10.16 4.45,12.7 1.27,10.16 1.27,27.94 48.26,10.16 45.72,12.7 48.9,21.59 25.4,35.56 26.04,46.99 26.04,49.53 26.04,44.45 32.38,44.45 32.38,46.99 32.38,49.53 30.56,45.54 30.56,43.66 28.07,50.16 28.07,52.7 30.61,50.16 30.61,48.26 27.04,35.87 27.04,37.73 27.04,39.38 29.74,36.32 29.74,34.72 27.65,40.98
  pour Bottom: 0,0 58.67,0 58.75,62.79 0.08,62.79
  pour Top (rank 2): 0,0 58.67,0 58.75,62.79 0.08,62.79
  pour IN2 (VDD) (isolate 0.254, rank 2): 0.15,61.52 0,0 58.67,0 58.67,61.52 32.11,61.52 32.11,34.42 32.46,34.42 33.05,33.83 33.05,33.07 31.29,31.32 31.29,29.84 29.26,29.84 29.24,31.93 31.45,34.26 31.57,34.42 31.88,34.42 31.9,34.44 32,61.52
  pour IN1 (GND) (isolate 0.254, rank 2): 0.18,61.54 0,0 58.67,0 58.65,61.52 32.08,61.52 32.01,34.42 32.47,34.42 33.05,33.84 33.05,33.08 32.45,32.48 31.68,32.48 31.05,33.12 31.04,33.84 31.62,34.42 31.98,34.42 31.91,34.45 31.98,61.52 31.96,61.54
GPIO0  (via drill 0.41, 0.41 pad 0.81)
  Top 0.203: 23.19,33.17 arc90 SJ4.2 | 15.7,34.34 15.72,34.31 | 15.29,34.34 14.9,34.73 R7.1
  Top 0.254: GPIO0.1 13.98,35.52 R7.1 | R8.2 13.28,26.09 v14.05,26.09 | 23.19,33.17 19,33.17 16.87,33.17 15.72,34.31 | 15.29,34.34 15.7,34.34
  IN1 (GND) 0.254: v50.67,6.63 50.6,6.33 48.74,6.33 47.02,8.05 45.72,8.05 43.28,8.05 42.27,9.07 37.67,9.07 35.97,10.77 30.89,10.77 30.79,10.87 30.23,11.43 27.56,11.43 v27.56,11.51
  IN2 (VDD) 0.254: GPIO0.1 13.34,35.53 13.59,35.53 14.28,34.85 14.28,34.39 14.28,33.81 14.28,29.59 13.18,28.5 13.18,26.09 | 13.18,26.09 v14.05,26.09 | 13.18,26.09 13.18,22.4 13.56,22.02 15.7,19.89 19.96,19.89 21.92,17.93 21.92,17.25 21.64,16.97 21.54,16.87 21.54,15.93 22.28,15.19 23.29,15.19 26.98,11.51 v27.56,11.51 | 13.18,26.09 13.18,25.96 | 13.18,26.09 13.18,25.96 | 13.18,26.09 13.18,25.96
  Bottom 0.254: CS1.6 48.46,3.96 49.84,5.33 50.67,6.17 v50.67,6.63
GPIO1  (via drill 0.41, 0.41 pad 0.81)
  Top 0.203: 26.19,29.16 26.31,29.16 26.19,29.16
  Top 0.254: 26.19,29.16 IC1.25 | 26.19,29.16 25.58,29.77 25.58,30.28 25.58,30.43 25.04,30.96 23.93,32.08 19.13,32.08 | GPIO1.1 13.41,32.08 14.22,32.08 18.95,32.08 19.1,32.08 | 19.1,32.08 19.13,32.08 | v22.96,41.94 SJ8.1 | 19.13,32.08 v19.23,32.36 | 19.1,32.08 19.13,32.08
  IN2 (VDD) 0.254: GPIO1.1 11.3,31.8 11.3,27.69 5.66,22.05 5.64,22.02 5.64,19.86 6.66,18.85 7.47,18.85 8.05,18.26 8.05,17.45 8.05,11.73 8.05,10.44 8.05,10.41 v8.05,8.66 | v22.96,41.94 19.23,38.2 19.23,33.27 v19.23,32.36
  Bottom 0.254: SJ5.1 7.77,8.2 8.05,8.48 v8.05,8.66
GPIO2  (via drill 0.41)
  Top 0.254: IC1.26 25.95,28.66 25.65,28.96 25.07,29.54 25.07,29.77 25.07,30.2 24.82,30.45 23.7,31.57 18.01,31.57 13.61,31.57 GPIO2.1 | v35.71,41.94 SJ10.2
  IN1 (GND) 0.254: v11.43,8.66 15.01,8.66 15.24,8.89 15.34,8.99 16,8.99 17.86,8.99 18.11,8.74 23.8,8.74 24.74,9.68 25.4,9.68 26.95,8.13 28.3,8.13 28.5,8.33 34.62,8.33 37.34,5.61 43.03,5.61 43.38,5.97 45.95,5.97 46.23,5.69 v46.28,5.64
  IN2 (VDD) 0.254: GPIO2.1 12.12,30.07 12.12,29.03 12.12,27.76 6.15,21.79 6.15,20.3 6.15,20.09 6.88,19.36 7.7,19.36 8.56,18.49 8.56,11.96 9.09,11.43 11.12,9.4 11.43,9.09 v11.43,8.66 | v46.28,5.64 51.79,11.15 53.82,11.15 54.36,11.68 54.36,20.57 54.05,20.88 54.05,21.74 54.36,22.05 54.36,23.29 53.06,24.59 53.06,29.11 54.66,30.71 54.66,33.15 45.87,41.94 v35.71,41.94
  Bottom 0.254: SJ6.1 v11.43,8.66
N$1
  Top 0.203: 30.1,32.44 LC.P$1
  Top 0.254: 30.07,32.23 30.1,32.26 30.1,32.44 30.1,32.56
  Top 0.305: 30.07,32.23 30.02,32.18 IC1.17
  Top 0.508: LC.P$1 C0.P$2
N$5  (via drill 0.41)
  Top 0.254: R7.2 13.98,33.02 13.72,33.29 13.72,34.24 v13.46,34.27
  IN2 (VDD) 0.254: CS1.29 19.18,2.69 19.18,5.28 19.18,5.56 17.35,7.39 17.27,7.47 15.32,7.47 14.78,8 10.64,12.14 10.08,12.7 10.08,19.71 8.59,21.21 8.13,21.21 7.7,21.64 7.7,22.48 12.68,27.46 12.68,28.73 13.72,29.77 13.72,33.63 13.72,34.01 v13.46,34.27
N$6
  Bottom 0.254: CS1.33 12.75,1.42 11.53,2.64 11.56,2.67 11.56,5.33 11.56,7.11 SJ6.2
N$8
  Bottom 0.254: CS1.37 6.66,2.52 6.5,2.67 6.5,5.23 6.66,5.38 6.66,6.45 7.09,6.88 7.44,7.24 SJ5.2
N$9  (via drill 0.41, 0.41 pad 0.81)
  Top 0.254: v14.5,24.23 13.24,24.23 R8.1
  IN1 (GND) 0.254: v32.59,12.52 32.82,12.39 36.47,12.39 37.13,11.76 37.47,11.43 38.28,10.62 39.78,10.62 41.1,10.62 46.28,10.62 46.33,10.62 49.02,7.92 49.71,7.92 v50.06,7.57
  IN2 (VDD) 0.203: 24.08,16.89 24.08,16.69
  IN2 (VDD) 0.254: v14.5,24.23 14.5,22.58 16.18,20.9 20.42,20.9 24.08,17.25 24.08,16.89 24.08,16.69 24.08,15.93 27.13,12.88 28.22,12.88 29.06,12.04 29.06,10.36 29.57,9.86 30.28,9.86 32.59,12.17 v32.59,12.52
  Bottom 0.254: CS1.7 47.12,2.69 47.12,4.04 47.12,4.32 47.98,5.18 48.74,5.18 49.89,6.33 49.89,7.39 v50.06,7.57
N$11
  Top 0.508: C0.P$1 L0.P$2 LH.P$2 CH.P$1
N$13
  Top 0.203: 20.8,34.36 Q4.4 21.72,34.37 22,34.37
  Top 0.254: 20.8,34.36 17.05,38.08 C20.1 | SJ3.1 23.24,34.77 23.22,34.75 22,34.75 22,34.37
N$14
  Top 0.508: CC2.P$1 CM2.P$1 LM2.P$2
N$19
  Top 0.203: SJ4.1 SJ3.2
  Top 0.254: IC1.24 26.4,29.66 26.09,29.97 26.09,30.63 26.09,30.66 24.33,32.41 24,32.74 SJ4.1
N$20
  Top 0.305: IC1.18 29.52,32.36 28.68,33.17 28.35,33.17 LR.P$2
  Top 0.508: LR.P$2 CR2.P$2
N$22
  Top 0.305: IC1.19 29.02,32.07 28.83,32.26 28.45,32.26 28.4,32.31 28.37,32.28 LR.P$1
  Top 0.508: CR1.P$1 LR.P$1
N$23
  Top 0.508: LC.P$2 RDC.P$1
N$25
  Top 0.305: CC2.P$2 IC4.5
  pour Top (rank 2, no thermals): 29.18,41.68 29.06,42.55 29.62,42.55 29.49,41.68
N$26
  Top 0.254: C20.2 13.12,38.08 TP4.1
N$29
  Top 0.254: IC4.6 SJ8.2
N$32
  pour Top (no thermals): 29.84,38.73 29.84,40.34 30.15,40.34 30.38,39.29
N$33
  Top 0.508: CH.P$2 LH.P$1 RH.P$2
N$34
  Top 0.254: Q3.3 35.24,29.28 35.2,29.23 35.14,29.66 IC1.12
N$35
  Top 0.152: 34.19,30.15 34.34,30.3 36.2,30.3
  Top 0.203: IC1.13 32.15,30.18 32.21,30.15 | 37.09,30.75 Q3.1 36.9,30.8 36.4,30.3 36.2,30.3
  Top 0.254: 32.21,30.15 34.19,30.15
N$36
  Top 0.203: 27.03,28.17 27.04,28.16 IC1.27
  Top 0.254: C16.P$1 24.59,28.8 24.94,28.8 25.58,28.17 27.03,28.17
  Top 0.305: C17.P$1 24.46,29.64 24.43,29.52 24.43,29.06 C16.P$1
N$38
  Top 0.254: IC4.4 SJ10.1
N$39
  Top 0.508: CC1.P$2 LM.P$1
N$41
  Top 0.305: IC2.3 6.47,15.25 R5.2 R4.1
N$45
  Top 0.254: IC1.1 32.41,24.16 32.74,23.82 34.34,22.23 35.38,22.23 35.61,22 Q1.X2
N$46
  Top 0.254: Q1.X1 32.74,21.8 32.84,22.2 32.38,22.2 32.26,22.3 31.02,23.55 IC1.42
N$48
  Bottom 0.254: CS1.13 38.25,1.42 39.42,2.59 39.52,2.69 39.52,4.37 39.52,6.76 SJ9.2
NIRQ  (via drill 0.41, 0.41 pad 0.81)
  Top 0.254: IC1.11 31.93,29.16 | IC1.11 | IC1.11 33.88,29.16 34.21,29.16 35.51,27.86 36.09,27.28 37.29,27.28 37.87,27.28 37.97,27.28 39.32,28.63 39.32,33.25 40.22,34.15 R12.2 41.52,34.15 NIRQ.1
  IN1 (GND) 0.254: CS1.12 41.91,5.11 44.65,5.11 44.83,5.11 v44.88,5.16
  IN2 (VDD) 0.254: v45.54,8.97 45.16,9.35 43.79,10.72 43.79,10.74 43.79,16.82 45.16,18.19 45.97,19 50.32,19 50.95,19.63 50.95,20.32 50.95,27.61 45.24,33.33 43.43,33.33 42.19,34.57 42.11,34.57 NIRQ.1
  Bottom 0.254: v44.88,5.16 44.93,5.36 44.93,5.99 45.9,6.96 46.18,7.24 SJ1.2 46.89,7.24 47.09,7.44 47.12,7.47 47.12,8.66 46.81,8.97 v45.54,8.97
NRST/C2CK  (via drill 0.41, 0.41 pad 0.81)
  Top 0.203: v42.42,17.4 42.06,17.4 | 43.56,17.37 R18.2 | 41.73,17.4 41.76,17.4
  Top 0.254: IC1.39 29.52,22.89 31.19,21.21 31.19,19.99 32.03,19.15 32.05,19.13 32.33,19.13 35.26,19.13 v35.59,18.8 35.84,18.54 36.68,18.54 36.85,18.54 37.16,18.85 40.16,18.85 41.6,17.4 41.73,17.4 | 43.56,17.37 43.38,17.4 v42.42,17.4 41.76,17.4
  IN1 (GND) 0.254: CS1.40 4.52,4.65 4.52,6.48 5.89,7.85 14.94,7.85 15.57,8.48 17.65,8.48 17.91,8.23 24.46,8.23 v25.07,8.87 | v50.16,21.29 50.67,20.65 52.58,18.75 54.3,18.75 J1.7 56.82,21.26 56.82,24.51 51.41,29.92 v50.65,29.92
  IN2 (VDD) 0.254: v25.07,8.87 25.58,8.87 25.93,8.87 27.28,10.21 28.5,10.21 29.36,9.35 30.58,9.35 31.52,10.29 33.66,12.42 33.66,17.37 34.52,18.24 35.08,18.8 v35.59,18.8 | v42.42,17.4 43.18,18.16 43.38,18.36 43.38,19.84 44.2,20.65 49.53,20.65 v50.16,21.29 | NRST/C2CK.1 44.91,34.57 45.57,33.91 49.55,29.92 v50.65,29.92
P0.0  (via drill 0.41)
  Top 0.254: v28.02,22.73 IC1.36
  IN1 (GND) 0.254: v49.07,7.11 46.13,10.06 46.08,10.11 44.86,10.11 40.89,10.11 39.57,10.11 38.05,10.11 36.42,11.73 31.9,11.73 v31.27,12.37 | P0.0.1 30.99,15.8 32.77,15.8 32.72,15.9 v32.72,15.8
  IN2 (VDD) 0.203: 27.99,22.53 28.02,22.55 v28.02,22.73
  IN2 (VDD) 0.254: v28.02,22.73 28.02,21.69 27,20.68 26.06,19.74 26.06,18.67 26.59,18.14 27.13,17.6 28.37,17.6 28.42,17.55 29.52,16.46 30.38,16.46 P0.0.1 | v32.72,15.8 32.72,13.79 v31.27,12.37
  Bottom 0.254: CS1.8 46.05,4.01 49.07,7.04 v49.07,7.11
P0.1  (via drill 0.41, 0.41 pad 0.81)
  Top 0.203: 27.1,24.16 IC1.35
  Top 0.254: 27.1,24.16 26.24,23.29 25.91,22.96 25.17,22.96 24.69,23.44 24.69,24.51 24.05,25.15 18.97,25.15 17.75,23.93 17.75,18.87 17.75,18.77 18.62,17.91 18.95,17.58 19.07,17.58 21.08,17.58 v21.12,17.61 21.16,17.58 21.79,17.58 26.01,17.58 27.18,16.41 P0.1.1 27.58,16.41
  IN1 (GND) 0.254: v44.07,8.84 43.31,9.6 37.85,9.6 36.91,10.54 36.2,11.25 31.19,11.25 31.06,11.38 30.15,12.29 30.1,12.34 26.14,12.34 25.7,12.78 24.99,12.78 24.43,12.22 v24.28,11.99
  IN2 (VDD) 0.254: v21.12,17.61 21.08,17.58 19.48,17.58 18.97,17.07 18.97,16 19.74,15.24 20.83,14.15 22.89,14.15 24.28,12.75 v24.28,11.99
  Bottom 0.254: SJ1.1 46,8.05 45.31,8.05 44.5,8.87 v44.07,8.84 43.69,8.46 43.69,7.57 43.69,6.93 43.59,6.83 43.31,6.55 43.31,6.43 CS1.10
P0.2  (via drill 0.41, 0.41 pad 0.81)
  IN1 (GND) 0.254: 38.73,8.38 v38.86,8.28 37.74,8.28 36.2,9.83 35.74,10.29 30.71,10.29 30.25,10.29 v29.9,10.64
  IN2 (VDD) 0.254: v15.44,22.81 15.44,22.38 16.41,21.41 20.65,21.41 22.33,19.74 25.43,16.64 P0.2.1 | P0.2.1 25.38,15.44 | 25.38,15.44 25.35,16.15 | v29.9,10.64 29.67,10.87 29.67,12.27 28.65,13.28 28.52,13.41 27.38,13.41 25.38,15.44 | P0.2.1 25.38,15.44
  Bottom 0.254: 38.25,3.96 CS1.14 | CS1.14 38.2,3.96 | SJ11.2 16.18,23.39 15.67,22.89 v15.44,22.81 | 38.25,3.96 CS1.14 | 38.25,3.96 38.73,4.45 38.86,4.57 38.86,4.6 v38.86,8.28
P0.2/XTAL1  (via drill 0.41)
  Top 0.203: 26.42,24.66 26.47,24.66 | IC1.34 26.98,24.66 26.97,24.66 | 25.81,24.05 25.83,24.08
  Top 0.254: 26.47,24.66 26.97,24.66 | 25.83,24.08 26.42,24.66 | v25.5,23.77 25.81,24.05
  Bottom 0.254: v25.5,23.77 25.36,23.76 24.73,24.41 C26.1 23.76,25.23 22,23.47 20.85,23.47 20.34,23.98 Q5.2 20.24,24.11 19.25,23.06 17.48,23.06 17.04,23.06 arc-90 SJ11.1 16.89,24.11 R20.2
P0.3  (via drill 0.41 pad 0.81)
  IN2 (VDD) 0.254: CS1.22 28.07,6.27 27.1,7.24 25.27,7.24 24.28,8.23 24.28,9.22 24.74,9.68 25.98,9.68 27.03,10.72 27.2,10.72 27.94,10.72 28.42,11.2 28.42,11.84 27.91,12.34 26.9,12.34 22.81,16.43 | 22.81,16.43 P0.3.1 22.81,16.43 | 22.81,16.43 22.81,17.78 20.22,20.37 20.17,20.4 16.48,20.4 15.93,20.4 13.72,22.61 13.72,24.59 15.9,26.77 v15.9,27.64
  Bottom 0.254: SJ12.2 15.9,27.99 v15.9,27.64
P0.3/XTAL2  (via drill 0.41)
  Top 0.254: IC1.33 25.74,25.16 v25.5,24.87
  IN2 (VDD) 0.203: 25.6,24.92 v25.5,24.87 25.5,25.45 22.15,28.8
  IN2 (VDD) 0.254: Q5.1 22.15,28.8
  Bottom 0.254: v25.5,24.87 25.53,24.84 25.58,24.84 26.29,24.11 26.29,23.34 25.76,22.84 24.87,22.84 23.93,21.89 R19.1 | R20.1 SJ12.1 16.89,28.98 | C27.1 16.89,29.81 16.89,28.98 | 16.89,28.98 19.41,28.98 19.99,28.98 Q5.1
P0.4  (via drill 0.41, 0.41 pad 0.81)
  Top 0.203: 26.96,25.65 IC1.32 arc90 IC1.32
  Top 0.254: 26.96,25.65 20.78,25.65 18.75,25.65 17.25,24.16 17.25,22.12 17.25,18.75 17.25,18.54 17.27,18.52 18.54,17.25 18.87,16.92 18.92,16.92 19.63,16.92 20.14,16.41 P0.4.1
  IN1 (GND) 0.254: v44.48,7.26 44.07,7.26 43.33,7.26 42.95,7.64 42.55,8.05 41,8.05 40.44,7.49 37.82,7.49 37.8,7.49 37.24,8.05 35.97,9.32 35.48,9.8 30.43,9.8 29.62,9.8 28.8,10.62 28.7,10.72 28.27,10.72 27.96,10.72 27.2,10.72 26.21,11.71 25.6,11.71 v25.35,11.99 25.32,12.01
  IN2 (VDD) 0.254: 20.24,16.38 P0.4.1 22.02,14.66 23.09,14.66 25.35,12.39 v25.35,11.99
  Bottom 0.254: CS1.9 44.6,2.72 44.6,4.29 44.04,4.85 44.04,5.99 44.48,6.43 v44.48,7.26
P0.5  (via drill 0.41)
  Top 0.203: IC1.31 IC1.31 arc90 IC1.31 | 16.74,18.39 16.74,18.44 | 26.95,26.16 IC1.31
  Top 0.254: 26.95,26.16 25.3,26.16 20.6,26.16 18.52,26.16 16.74,24.38 16.74,22.3 16.74,18.44 | 16.74,18.39 16.74,17.4 P0.5.1
  IN1 (GND) 0.254: v41.35,7.26 41.07,6.99 37.57,6.99 37.49,7.06 35.74,8.81 35.2,9.32 30.23,9.32 29.39,9.32 28.5,10.21 27.99,10.21 27.69,10.21 27,10.21 26.01,11.2 24.36,11.2 24.08,11.2 23.57,11.2 23.55,11.23 v23.57,11.18
  IN2 (VDD) 0.254: P0.5.1 18.31,15.82 19.43,14.71 20.52,13.61 22.66,13.61 23.5,12.78 23.5,11.81 23.5,11.25 v23.57,11.18
  Bottom 0.254: CS1.11 40.74,1.42 42.04,2.72 42.04,4.55 41.35,5.26 v41.35,7.26
P0.6  (via drill 0.41, 0.41 pad 0.81)
  Top 0.203: IC1.30
  Top 0.254: IC1.30 20.4,26.67 18.29,26.67 16.23,24.61 16.23,22.48 16.23,17.5 15.19,16.46 P0.6.1
  IN1 (GND) 0.254: v27.94,8.91 27.66,9.2 26.59,9.2 25.6,10.19 24.51,10.19 23.9,9.58 v23.52,9.58
  IN2 (VDD) 0.203: CS1.15 35.71,1.42 | 30.05,2.72 30.15,2.72
  IN2 (VDD) 0.254: CS1.15 34.39,2.72 30.15,2.72 | 30.05,2.72 29.34,3.43 29.34,7.52 v27.94,8.91 | P0.6.1 17.42,14.17 18.52,13.08 21.87,13.08 22.78,12.17 22.78,10.85 23.52,10.11 v23.52,9.58
P0.7  (via drill 0.41)
  Top 0.152: 27.05,27.18 IC1.29
  Top 0.203: 27.05,27.18 27.08,27.15
  Top 0.254: 27.05,27.18 20.19,27.18 18.06,27.18 15.72,24.84 15.32,24.43 15.32,23.85 14.66,23.19 14.66,22.43 15.7,21.39 15.7,18.9 15.7,18.69 14.88,17.88 13.41,16.41 P0.7.1
  IN1 (GND) 0.254: CS1.2 52.3,5.13 47.93,5.13 46.58,6.48 43.16,6.48 42.82,6.15 41.96,6.15 41.88,6.15 41.55,6.48 37.34,6.48 35.51,8.31 34.98,8.84 30.02,8.84 29.16,8.84 28.3,9.7 27.94,9.7 27.43,9.7 26.8,9.7 25.81,10.69 24.31,10.69 24,10.39 22.94,10.39 v22.5,9.96
  IN2 (VDD) 0.254: P0.7.1 15.42,13.64 16.48,12.57 21.64,12.57 22.25,11.96 22.25,10.67 22.25,10.21 v22.5,9.96
P1.5  (via drill 0.41)
  Top 0.254: IC1.10 33.75,28.66 34.03,28.66 35.46,27.23 35.64,27.05 35.92,26.77 37.72,26.77 38,26.77 38.63,26.77 v39.55,27.69 39.55,27.96 39.83,28.25 40.08,28.5 40.08,29.92 41.63,31.47 41.63,31.62 P1.5.1
  IN1 (GND) 0.254: CS1.24 25.5,3.96 26.44,3.96 27.58,5.11 28.98,5.11 31.42,5.11 v31.88,4.65
  IN2 (VDD) 0.254: v39.55,27.69 39.4,27.48 39.4,26.29 39.4,24.38 38.18,23.16 36.7,21.69 36.7,21.59 36.7,20.47 37.31,19.86 37.31,16.05 37.31,12.22 32.23,7.14 32.23,6.63 32.23,5 v31.88,4.65
P1.6  (via drill 0.41)
  Top 0.254: P1.6.1 43.36,30.79 41.68,30.79 40.92,30.02 40.87,29.97 v40.87,28.63 40.87,28.42 40.84,28.4 40.36,27.91 40.36,27.38 39.24,26.26 38.61,26.26 38.15,26.26 36.6,26.26 36.14,26.26 35.74,26.26 35.64,26.36 33.84,28.16 33.54,28.16 IC1.9
  IN1 (GND) 0.254: v14.12,5.49 14.25,5.61 14.81,5.61 16.03,5.61 16.41,5.23 16.82,5.23 17.2,5.61 18.59,5.61 20.4,5.61 20.88,5.13 21.13,4.88 21.39,4.62 22.05,4.62 22.53,5.11 26.9,5.11 27.38,5.59 32.05,5.59 32.54,5.11 33.6,5.11 34.04,4.67 34.8,4.67 35.13,5 35.51,5.38 v35.48,5.38
  IN2 (VDD) 0.203: v35.48,5.38 35.51,5.38 | 39.9,25.43 39.9,25.45
  IN2 (VDD) 0.254: 39.9,25.43 39.9,24.99 39.9,21.08 39.34,20.52 39.34,11.91 39.34,11.38 38.28,10.31 35.79,7.82 35.79,7.29 35.79,6.15 35.79,5.66 35.51,5.38 | 39.9,25.45 40.54,26.09 40.87,26.42 v40.87,28.63
  Bottom 0.254: v14.12,5.49 12.83,4.19 CS1.34
P1.7  (via drill 0.41)
  Top 0.254: IC1.8 33.33,27.66 33.68,27.66 35.43,25.91 35.59,25.76 37.36,25.76 38.76,25.76 39.47,25.76 40.87,27.15 40.87,27.46 42.09,28.68 P1.7.1 | P1.7.1 42.09,29.36 | P1.7.1 42.09,29.08
  IN1 (GND) 0.254: v9.83,6.43 10.21,6.81 13.54,6.81 15.39,6.81 16.03,7.44 17.2,7.44 17.25,7.39 17.35,7.29 17.42,7.21 18.19,7.21 26.16,7.21 26.57,7.62 28.52,7.62 28.73,7.82 34.29,7.82 36.7,5.41 37.11,5 v37.11,4.9
  IN2 (VDD) 0.254: 40.39,15.49 40.39,12.09 | 40.39,15.49 40.39,20.09 40.92,20.62 40.92,22.48 41.63,23.19 42.9,23.19 43.36,23.65 43.36,26.42 43.36,27.53 43.36,28.25 P1.7.1 | 40.39,15.49 40.39,10.97 38.43,9.02 38.38,8.97 37.11,7.7 37.11,7.19 v37.11,4.9
  Bottom 0.254: v9.83,6.43 9.83,4.37 10.36,4.01 10.31,3.96 CS1.36
P2.0(P0.7)  (via drill 0.41)
  Top 0.254: IC1.7 33.12,27.16 33.52,27.16 35.41,25.27 35.43,25.25 37.49,25.25 37.59,25.25 38.96,25.25 39.7,25.25 41.43,26.98 P2.0.1 43.36,28.25 v46.58,28.25
  IN1 (GND) 0.254: v53.87,25.15 53.31,25.7 v50.16,25.7
  IN2 (VDD) 0.254: CS1.3 51.31,1.42 51.99,2.11 52.58,2.69 53.49,2.69 53.82,2.69 54.63,3.5 56.77,5.64 57.3,6.17 57.3,23.09 56.62,23.77 54.81,23.77 53.87,24.71 v53.87,25.15 | v50.16,25.7 49.12,25.7 v46.58,28.25
P2.1(P1.4)  (via drill 0.41)
  Top 0.254: IC1.6 33.34,26.66 35.15,24.84 35.26,24.74 37.74,24.74 39.57,24.74 40.34,24.74 v41.3,25.7 42.65,25.7 43.92,26.98 P2.1.1
  IN2 (VDD) 0.203: 36.3,4.57 36.3,4.58
  IN2 (VDD) 0.254: v41.3,25.7 40.41,24.82 40.41,22.63 40.41,20.85 39.88,20.32 39.88,11.46 39.88,11.2 39.09,10.41 36.3,7.62 36.3,7.09 36.3,5.69 36.3,4.58 | CS1.16 36.3,4.57
P2.2(P1.5)  (via drill 0.41)
  Top 0.254: IC1.5 33.13,26.16 34.75,24.54 34.9,24.38 35.05,24.23 37.54,24.23 41.88,24.23 arc90 P2.2.1 42.32,24.43 42.55,24.66 43.59,25.7 45.11,25.7 45.82,26.42 v46.58,26.42
  IN1 (GND) 0.254: v55.04,25.15 54.15,24.28 v50.16,24.28
  IN2 (VDD) 0.254: CS1.1 55.17,3.12 57.3,5.26 57.81,5.77 57.81,23.34 57.3,23.85 56.84,24.31 55.88,24.31 v55.04,25.15 | 46.61,26.42 v46.58,26.42 48.72,24.28 v50.16,24.28
P2.3(P1.6)  (via drill 0.41)
  Top 0.254: IC1.4 32.94,25.66 34.57,24.03 34.72,23.88 34.87,23.72 37.06,23.72 40.92,23.72 41.1,23.72 41.63,23.19 43.38,23.19 P2.3.1 v46.58,24.43
  IN1 (GND) 0.254: v54.91,21.34 51.41,21.34 v50.14,22.61
  IN2 (VDD) 0.203: 49.63,2.67 49.66,2.69
  IN2 (VDD) 0.254: CS1.5 49.63,2.67 | 49.66,2.69 49.66,4.45 50.34,5.13 55.47,5.13 56.77,6.43 56.77,20.75 56.19,21.34 v54.91,21.34 | v50.14,22.61 48.41,22.61 v46.58,24.43
P2.4  (via drill 0.41)
  Top 0.254: 32.78,25.16 32.65,25.16 | 32.78,25.16 32.65,25.16 | 32.65,25.16 IC1.3 | 41.96,21.89 P2.4.1 41.07,22.91 v39.12,22.91 38.81,23.22 36.25,23.22 35.51,23.22 34.72,23.22 34.57,23.37 34.42,23.52 32.78,25.16 | 32.78,25.16 32.65,25.16
  IN1 (GND) 0.254: v21.72,5.41 21.82,5.61 26.7,5.61 27.18,6.1 32.28,6.1 32.77,5.61 34.29,5.61 v34.42,5.46
  IN2 (VDD) 0.203: 39.4,22.63 v39.12,22.91 | v34.42,5.46 34.39,5.46
  IN2 (VDD) 0.254: 39.4,22.63 39.4,21.34 38.84,20.78 38.84,15.67 38.84,11.58 37.62,10.36 35.28,8.03 35.28,7.49 35.28,6.55 35.28,6.33 v34.42,5.46
  Bottom 0.254: CS1.27 21.69,2.67 v21.72,5.41
P2.5  (via drill 0.41)
  Top 0.254: 32.62,24.66 32.52,24.66 | 32.62,24.66 32.52,24.66 | 32.52,24.66 IC1.2 | 32.62,24.66 32.52,24.66 | 32.62,24.66 34.27,23.01 34.42,22.86 34.57,22.71 35.46,22.71 35.56,22.71 37.69,22.71 v38.53,21.87 38.99,21.87 40.36,21.87 41.6,20.62 43.36,20.62 P2.5.1
  IN1 (GND) 0.254: v33.02,6.48 32.77,6.6 26.95,6.6 26.54,6.2 21.46,6.2 16.66,6.2 arc90 v16.61,6.15 16.74,6.27 16.89,6.12
  IN2 (VDD) 0.254: v38.53,21.87 38.33,21.82 38.33,21.61 38.33,21.11 38.33,20.9 38.33,20.65 38.33,11.91 38.33,11.81 38.33,11.79 37.62,11.07 34.77,8.23 34.77,7.7 34.77,7.26 34.77,6.76 34.77,6.6 34.42,6.25 34.27,6.25 33.93,6.25 33.25,6.25 v33.02,6.48
  Bottom 0.254: CS1.31 16.61,2.67 v16.61,6.15
P2.6  (via drill 0.41, 0.41 pad 0.81)
  Top 0.254: P2.6.1 40.56,20.88 40.36,21.08 v37.52,21.08 36.63,20.14 36.27,20.14 32.46,20.14 32.21,20.4 32.21,21.61 30.58,23.24 30.52,23.31 IC1.41
  IN1 (GND) 0.254: v8.99,5.49 9.53,5.61 9.93,5.61 13.11,5.61 13.79,6.3 15.62,6.3 16.26,6.93 16.97,6.93 17.02,6.88 17.12,6.78 17.2,6.71 17.75,6.71 26.34,6.71 26.75,7.11 28.85,7.11 29.03,7.29 33.68,7.29 v33.96,7.04
  IN2 (VDD) 0.254: 41.6,18.87 P2.6.1 41.4,18.67 41.4,18.01 41.4,17.25 43.18,15.47 43.18,10.41 43.18,9.5 43.18,7.64 43.18,7.47 42.95,7.24 42.7,7.24 v42.39,6.93 | v37.52,21.08 37.82,20.93 37.82,20.45 37.82,20.09 37.82,15.82 37.82,11.99 36.93,11.1 33.96,8.13 33.96,7.64 v33.96,7.04
  Bottom 0.254: 9.25,5.59 v8.99,5.49 9.14,5.49 9.14,2.56 CS1.35 | v42.39,6.93 SJ13.1
P2.7/C2D  (via drill 0.41, 0.41 pad 0.81)
  Top 0.203: 36.25,19.58 36.2,19.63
  Top 0.254: IC1.40 30.02,23.1 31.7,21.41 31.7,20.19 32.26,19.63 32.31,19.63 36.2,19.63 | 36.25,19.58 v36.5,19.36 40.44,19.36 41.6,18.19 42.6,18.19 43.54,19.13 43.76,19.36 44.6,19.36 | 44.6,19.36 P2.7/C2D.1 44.6,19.36
  IN1 (GND) 0.254: CS1.38 6.83,3.96 5.66,5.13 5.36,5.13 5.03,5.46 5.03,6.25 5.74,6.96 6.12,7.34 6.35,7.34 15.16,7.34 15.8,7.98 17.42,7.98 17.58,7.82 17.68,7.72 25.55,7.72 v25.83,8.03 | v50.16,19.99 50.9,19.36 51.82,18.44 51.82,16.26 J1.4
  IN2 (VDD) 0.254: v36.5,19.36 36.5,18.57 35.94,18.01 35.51,18.01 35.08,18.01 35,17.93 34.19,17.12 34.19,12.12 31.85,9.78 30.91,8.84 29.16,8.84 28.3,9.7 27.51,9.7 v25.83,8.03 | v50.16,19.99 45.24,19.99 P2.7/C2D.1
RX
  Top 0.457: CR2.P$1 28.35,39.29
  pour Top (no thermals): 28.14,39.34 28.52,40.31 28.83,40.31 28.83,39.57 28.55,39.17
SDN  (via drill 0.41, 0.41 pad 0.81)
  Top 0.254: v33.17,30.94 32.92,31.19 31.09,31.19 31.02,31.04 IC1.15 | SDN.1 44.67,29.5 44.67,30.27 45.44,31.04 45.47,31.06 45.8,31.06 arc60 R11.1 R2.2
  IN2 (VDD) 0.203: 33.2,30.91 v33.17,30.94
  IN2 (VDD) 0.254: v40.08,8.28 40.08,9.91 40.89,10.72 40.89,11.99 40.89,18.87 40.89,19.86 41.66,20.62 42.62,20.62 43.36,21.36 43.36,22.4 44.12,23.16 45.06,23.16 45.8,23.9 45.8,24.99 45.8,28.35 SDN.1 43.38,30.76 43.38,30.91 43.38,32.59 42.7,33.27 41.3,33.27 40.82,33.27 39.34,31.8 38.99,31.8 33.88,31.8 33.22,31.14 33.2,31.11 33.2,30.91
  Bottom 0.254: SJ9.1 40.01,8.18 v40.08,8.28 42.11,8.28 arc-90 SJ13.2
TX
  Top 0.457: CM3.P$1 ANT.1
  Top 0.508: CM3.P$1 LM2.P$1
TX3
  Top 0.508: LM.P$2 CM.P$1 L0.P$1
VCC_MCU  (via drill 0.41, 0.41 pad 0.81)
  Top 0.203: 26.2,22.43 L3.2 24.89,21.9 v24.97,21.67 25.48,21.67 25.48,21.86 | 27.84,21.82 C28.P$1 | C21.P$1 29.16,21.82
  Top 0.254: IC1.38 29.02,21.73 29.02,21.82 C21.P$1 | v46.01,17.78 R18.1 44.92,17.21
  Top 0.406: 29.16,21.82 29.72,21.82 30.58,20.95 30.58,20.02 30.58,19.66 32.36,17.88 35.23,17.88 39.57,17.88 40.18,17.88 41.73,16.33 44.2,16.33 44.53,16.33 44.91,16.71 44.92,17.21
  Top 0.508: C28.P$1 C21.P$1 | 27.84,21.82 26.53,21.82 L3.2
  Top 0.61: C25.1 25.48,21.86
  IN1 (GND) 0.254: J1.1 54.36,13.72 52.43,13.72 50.16,15.98 v50.16,18.14
  IN2 (VDD) 0.254: v50.16,18.14 46.37,18.14 v46.01,17.78
  Bottom 0.254: R19.2 25.59,21.72 v24.97,21.67
VDD  (via drill 0.41, 0.41 pad 0.81, 0.61 pad 0.81)
  Top 0.203: L3.1 26.04,20.26 26.01,19.71
  Top 0.254: 30.52,31.56 30.5,31.57 30.76,31.83 32.77,31.83 32.66,31.93 32.66,32.28 RDC.P$2 | R2.1 45.37,35.87 43.36,35.87 VDD.1
  Top 0.279: 30.52,31.56 IC1.16
  Top 0.406: C2.P$1 34.9,33.88 35.48,34.47 35.56,34.54 C3.P$1 35.74,35.39 C4.1 35.97,35.5 35.87,35.66
  Top 0.508: 34.19,32.51 33.35,32.51 | 34.19,32.51 33.35,32.51 | 34.19,32.51 C1.P$1 | 33.35,32.51 33.66,32.51 34.19,32.51 | 33.35,32.51 33.05,32.51 32.84,32.44 RDC.P$2 32.79,31.95 33.35,32.51 | C2.P$1 34.19,32.87 34.19,32.51
  Top 0.61: v26.98,19.51 26.01,19.71
  Top 0.813: v35.87,36.63 35.87,35.66 | 26.01,19.71 25.91,20.14 L4.1
  IN1 (GND) 0.61: v26.98,19.51 26.98,19.48 27.64,18.8 28.4,18.8 30.02,18.8 31.93,16.87 32.26,16.87 34.21,16.87 35.59,16.87 | v46.02,16.03 46.02,15.98 45.54,15.49 38.05,15.49 36.68,16.87 35.59,16.87 | 35.59,16.87 35.18,16.87 v35.61,16.66 35.59,16.87
  IN2 (VDD) 0.61: 42.04,37.13 VDD.1 | 42.04,37.13 39.62,37.13 36.37,37.13 v35.87,36.63 | 42.04,37.13 42.09,37.21 43.54,38.66 46.13,38.66 50.8,34.01 50.8,31.9 | CS1.18 32.74,3.58 30.99,3.58 CS1.20 30.61,7.06 35.61,12.06 v35.61,16.66 | 50.8,31.9 50.72,31.9 50.8,31.9 | 50.8,31.9 VDD2.1 51.74,30.94 51.74,17.8 49.96,16.03 v46.02,16.03
VDD_RF  (via drill 0.41 pad 0.81)
  Top 0.254: R12.1 40.26,31.65 v40.49,31.8 | IC1.28 26.98,27.69 25.65,27.69 24.11,27.69 v24.56,27.96
  Top 0.406: L4.2 21.97,19.97 v22.58,20.85 | C11.P$1 23.9,27.76 24,27.76 24.59,27.76 v24.56,27.96
  Top 0.813: L4.2 22.13,19.88 C24.1
  IN2 (VDD) 0.406: v24.56,27.96 27,25.53 27,21.67 25.2,19.86 24.6,19.27 24.4,19.27 | v40.49,31.8 40.49,29.9 38.63,28.04 38.63,27.74 38.63,24.54 38.43,24.33 36.04,21.95 36.04,20.62 31.77,16.36 31.77,15.72 31.14,15.09 27.36,15.09 26.62,15.82 26.62,17.04 25.2,18.47 24.4,19.27 | 24.4,19.27 22.81,20.85 v22.58,20.85

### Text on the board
tPlace: EZRadioPRO | 1000-TCB1 C 470 | GND | VDD | GND | EBID
bPlace: VDD | GND
tNames: IC1
bNames: VDD | GND | TP4 | NRST/C2CK | GPIO0 | NIRQ | GPIO1 | P1.6 | P1.5 | GPIO2 | SDN | P1.7 | P2.1 | P2.0 | P2.3 | P2.2 | P2.5 | P2.4 | P2.6 | P0.7 | P0.6 | P0.5 | P0.4 | P0.3 | P0.2 | P0.1 | P0.0 | P2.7/C2D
